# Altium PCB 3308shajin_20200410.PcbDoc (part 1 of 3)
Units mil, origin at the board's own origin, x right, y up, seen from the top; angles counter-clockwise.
Board outline 4724.41 x 2952.76 mil, 4 copper layers (Top, GND, Power, Bottom), stack 35.4 mil thick; 266 components, 266 nets, 1212 pads, 1516 vias.
Unrouted connection lines stored in the file: 149.
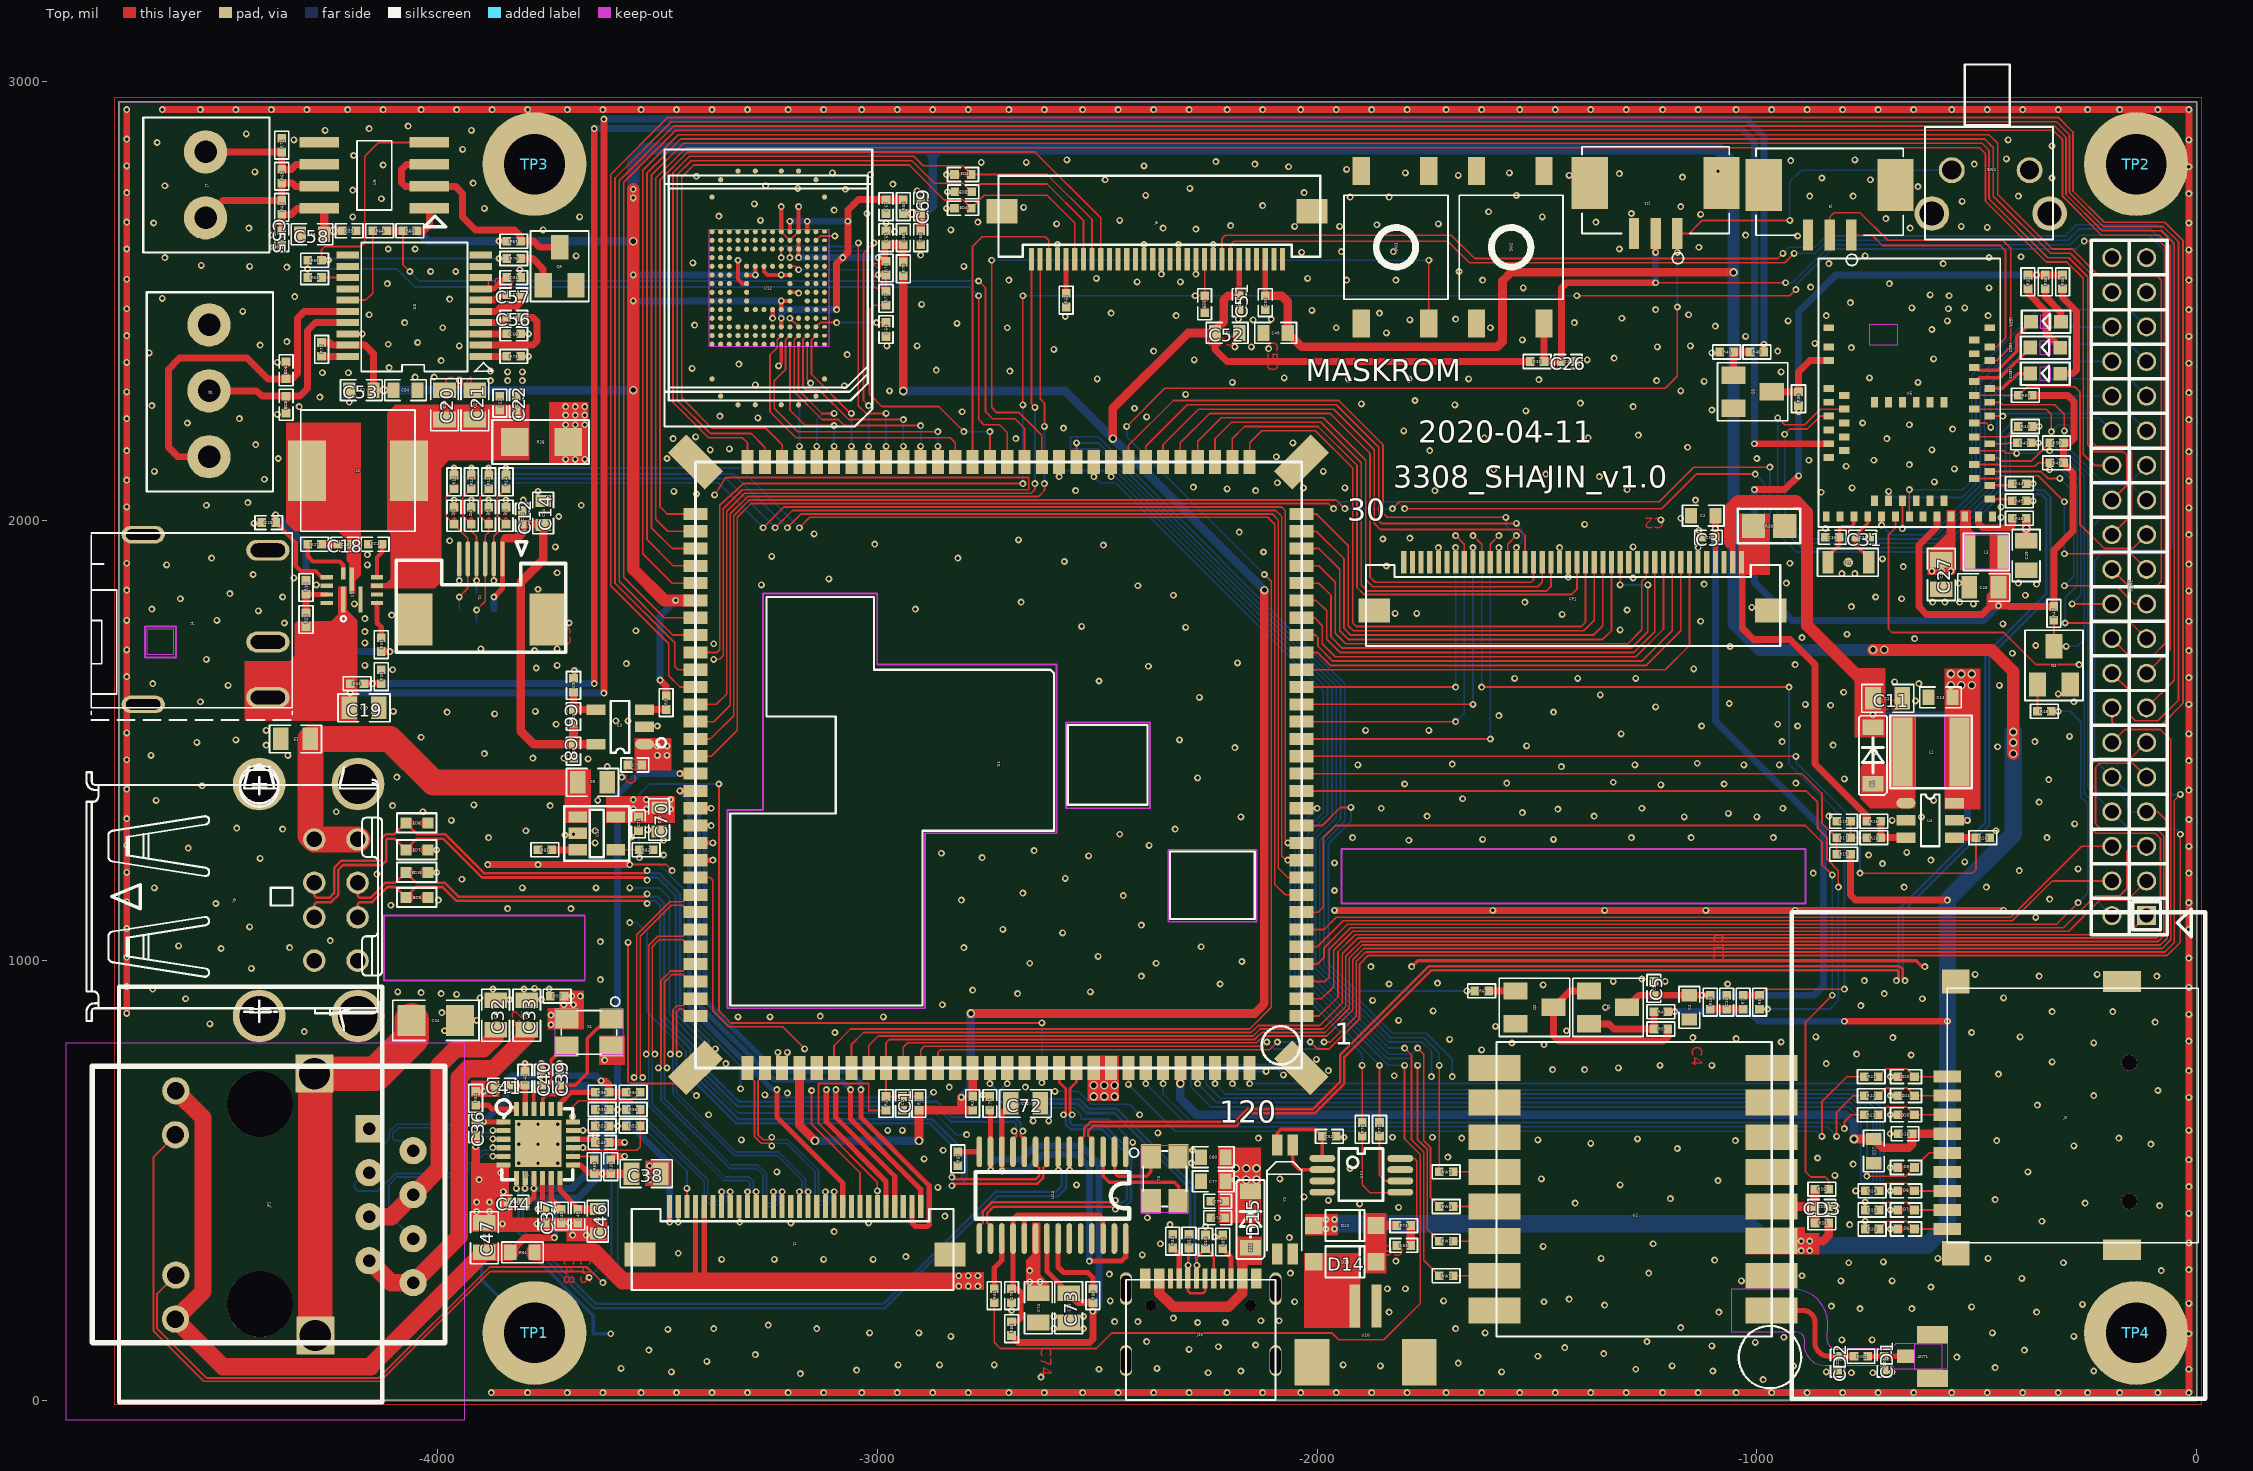
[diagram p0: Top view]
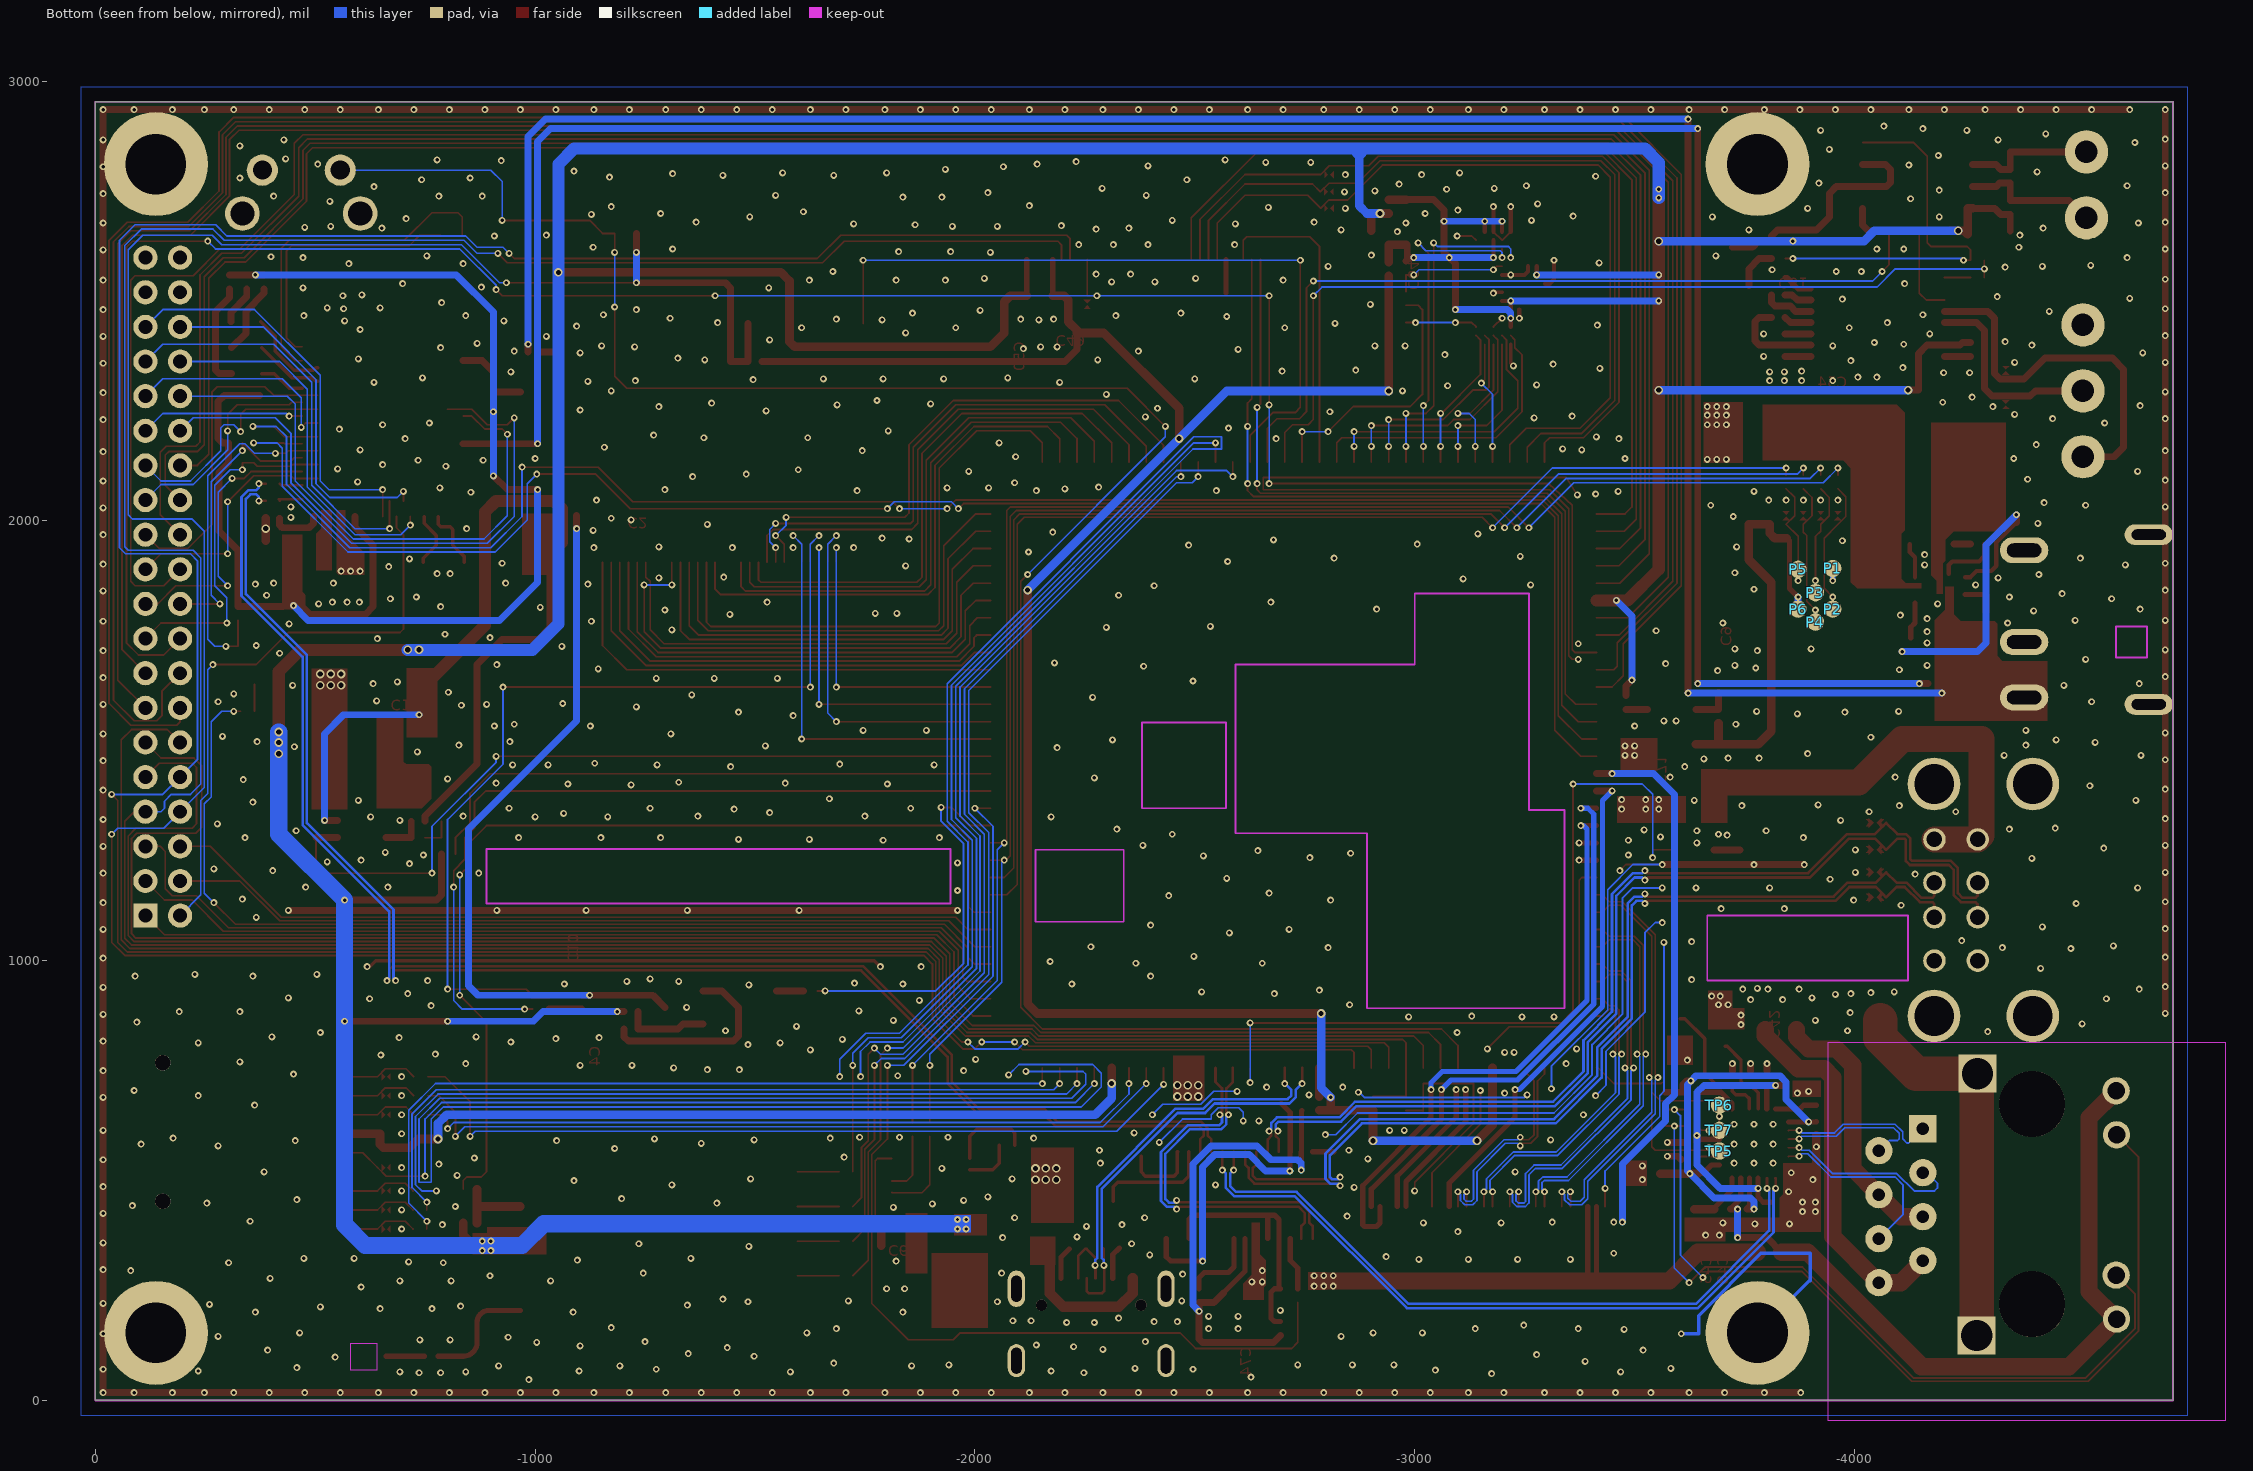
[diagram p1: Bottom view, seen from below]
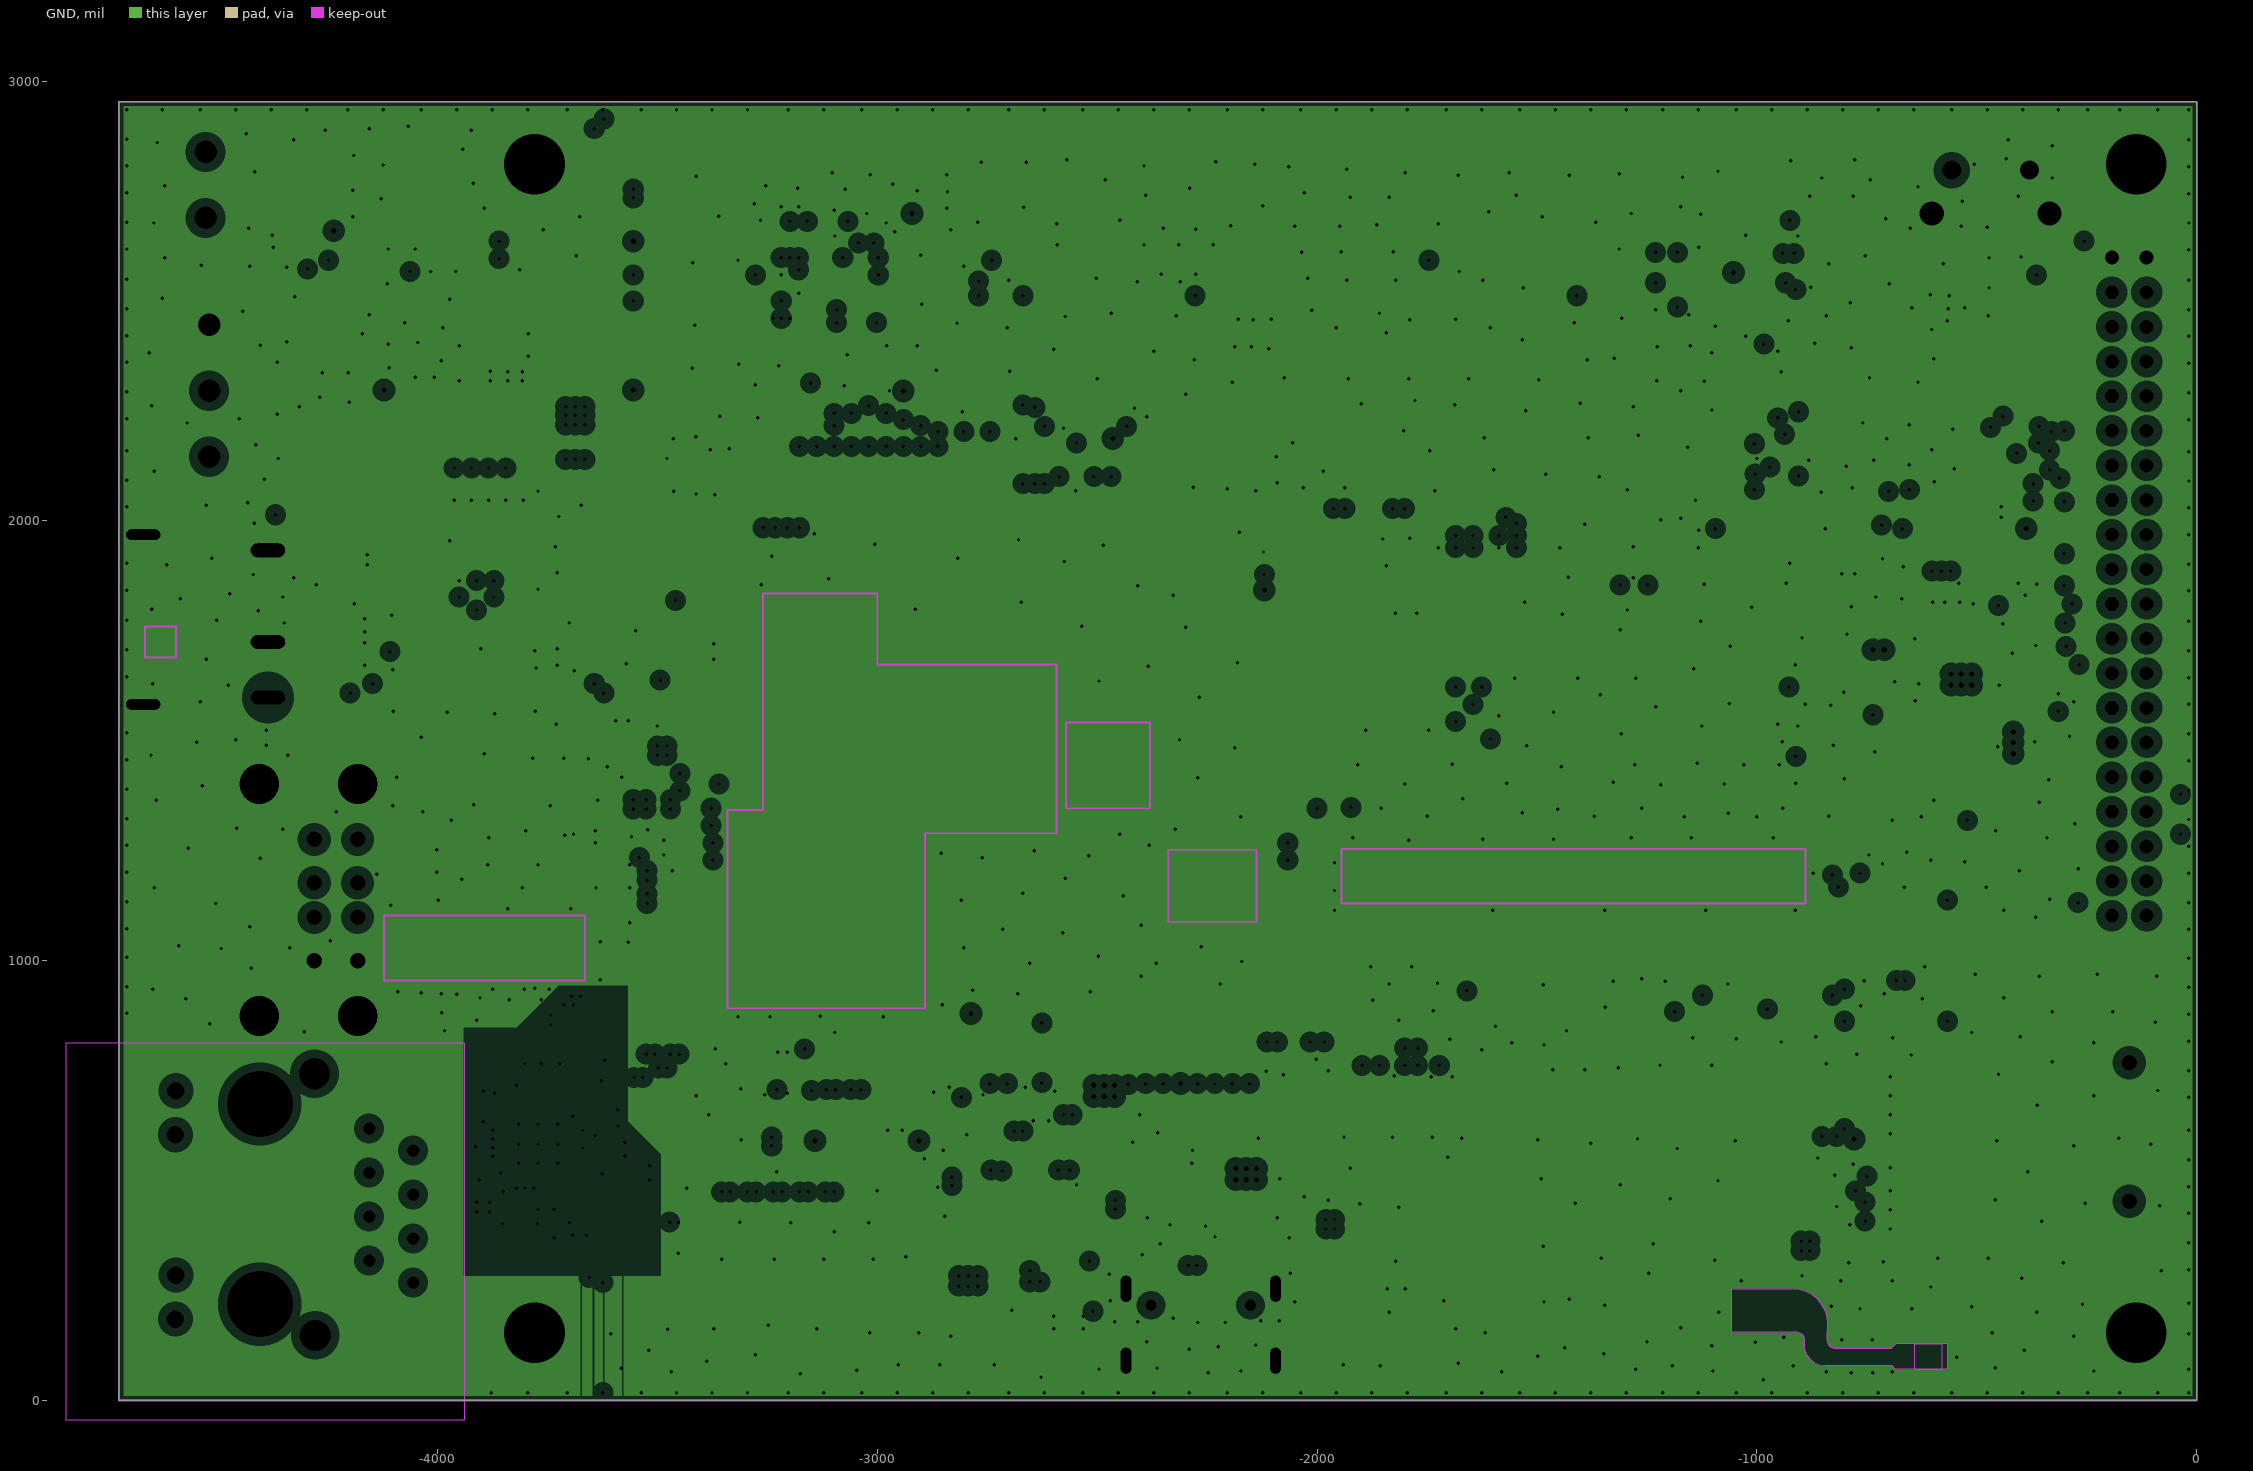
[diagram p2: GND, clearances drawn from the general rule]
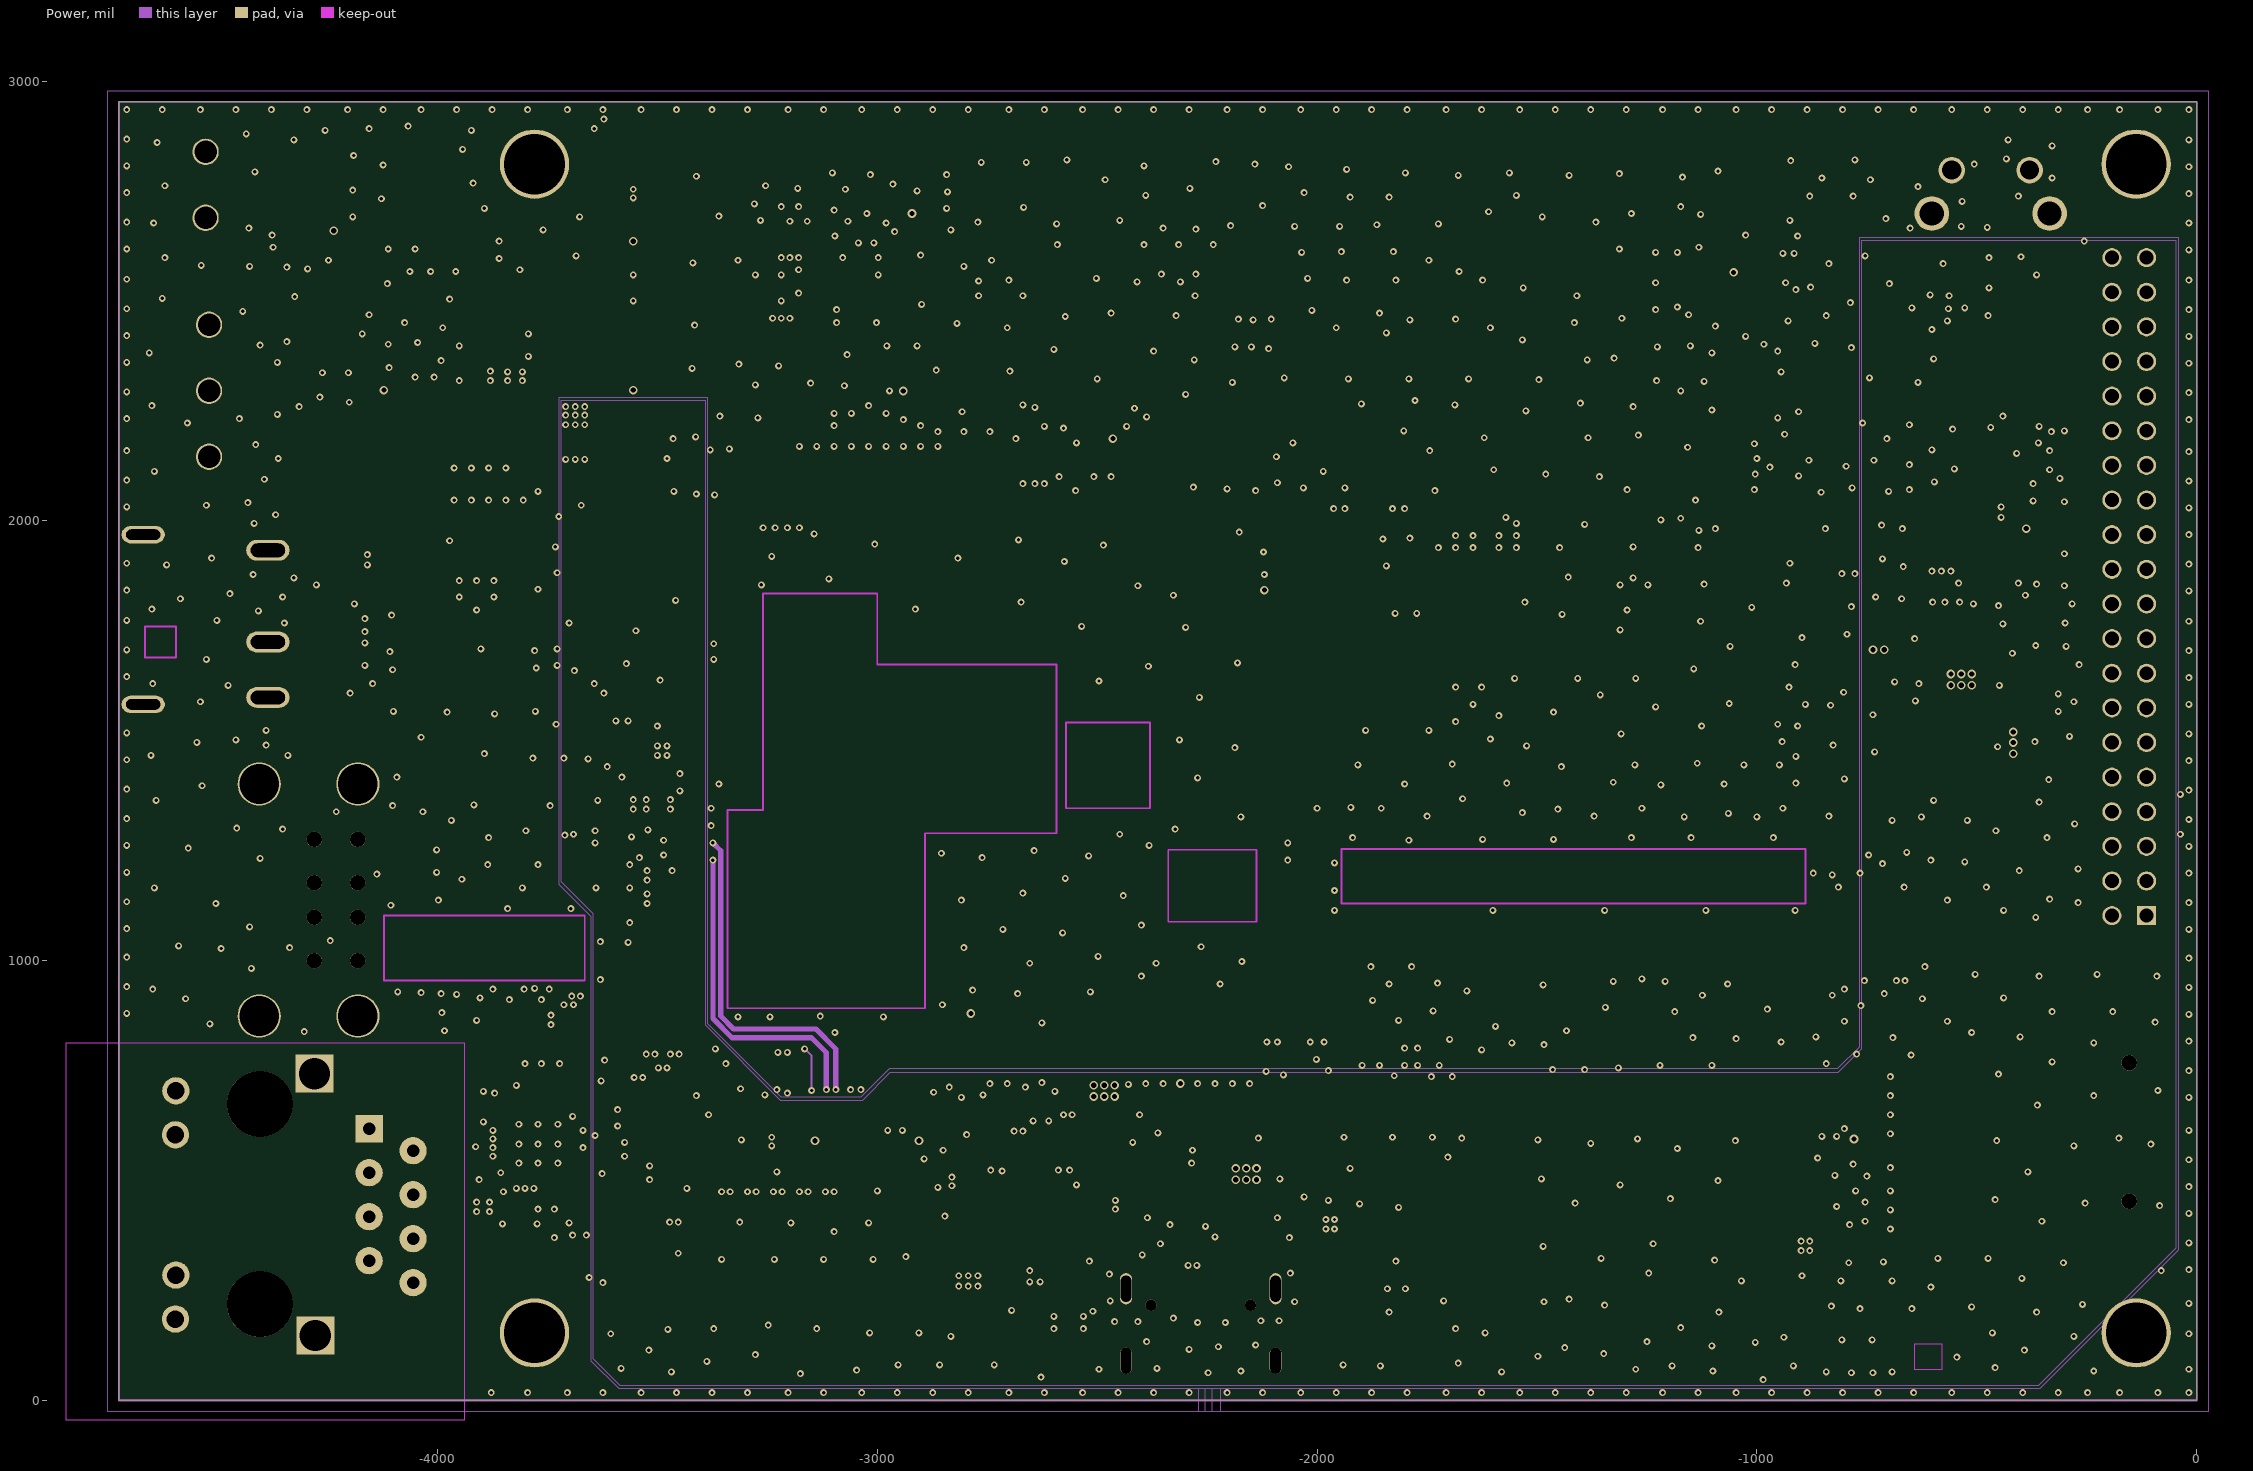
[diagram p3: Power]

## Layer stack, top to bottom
Solder Mask Top: solder mask 0.4, Solder Resist, Dk 3.5
Top: signal copper 1.35
Dielectric 1: dielectric 10, FR-4, Dk 4.3
GND: plane copper 1.35
Dielectric2: dielectric 10, FR-4, Dk 4.3
Power: signal copper 1.35
Dielectric3: dielectric 10, FR-4, Dk 4.3
Bottom: signal copper 1.35
Solder Mask Bottom: solder mask 0.4, Solder Resist, Dk 3.5

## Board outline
-4724.41,2952.76 0,2952.76 0,0 -4724.41,0

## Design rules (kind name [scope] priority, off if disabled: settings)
Clearance "Clearance - Default - DEFAULT- SMD" [IsVia vs IsSMTPin] p1: gap=0 ignorepadtopadclearanceinfootprint=FALSE
Clearance "Clearance - Default - DEFAULT - Via" [IsVia vs IsVia] p2: gap=0 ignorepadtopadclearanceinfootprint=FALSE
Clearance "Clearance - Default - DEFAULT - Net" [All] p3: gap=3.94 ignorepadtopadclearanceinfootprint=FALSE except(0: Arc-Hole Track-Hole SMDPad-Hole THPad-Hole Via-Hole Fill-Hole Poly-Hole Region-Hole Text-Hole; 5.91: Arc-Fill Arc-Poly Arc-Region Track-Fill Track-Poly Track-Region SMDPad-Fill SMDPad-Poly SMDPad-Region THPad-Fill THPad-Poly THPad-Region Via-Fill Via-Poly Via-Region; 10: Fill-Fill Fill-Poly Fill-Region Poly-Poly Poly-Region Region-Region Text-Text)
ComponentClearance "ComponentClearance - Default - DEFAULT" [All] p1: gap=0 collisioncheckmode=3 verticalgap=10 showdistances=FALSE
FanoutControl Fanout_Small [(CompPinCount < 5)] p3: bgadir=Out bgaviamode=Centered fanoutstyle=Auto fanoutdirection=OutThenIn viagrid=1 // Fanout_Small (Default Rule)
FanoutControl Fanout_SOIC [IsSOIC] p4: bgadir=Out bgaviamode=Centered fanoutstyle=Auto fanoutdirection=Alternating viagrid=1 // Fanout_SOIC (Default Rule)
HoleToHoleClearance "HoleToHoleClearance - Default - DEFAULT" [All] p1: gap=0 allowstackedmicrovias=TRUE
Length "Default Length" [All] p1: maxlimit=50000 minlimit=0
MaxMinImpedance "Default Impedance" [All] p1: minimum=50.00 maximum=150.0
ParallelSegment "Default Parallel Segment Adjasent" [All] p1: limit=1000 gap=200
ParallelSegment "Default Parallel Segment Same Layer" [All] p2: limit=1000 gap=200
PlaneClearance [All] p1: clearance=20
PlaneConnect "Default PlaneConnect" [All] p1: planeconnectstyle=Relief reliefexpansion=20 reliefentries=0 reliefconductorwidth=15 reliefairgap=10
PolygonConnect "PolygonConnect - Default SMT" [IsSMTPin] p1: connectstyle=Direct reliefconductorwidth=10 reliefentries=4 polygonreliefangle="45 Angle" airgapwidth=10
PolygonConnect "PolygonConnect - Default Pad" [All] p2: connectstyle=Relief reliefconductorwidth=15 reliefentries=4 polygonreliefangle="45 Angle" airgapwidth=10
RoutingLayers "RoutingLayers - Default - DEFAULT" [All] p1: top layer_v5=TRUE mid layer 1_v5=TRUE bottom layer_v5=TRUE
RoutingPriority "RoutingPriority - Default - DEFAULT" [All] p1: routingpriority=3
RoutingTopology "Default Routing Topology" [All] p1: topology=Shortest
RoutingVias "RoutingVias - Default - DEFAULT" [All] p1: holewidth=7.87 width=15.75 viastyle="Through Hole" minholewidth=7.87 minwidth=15.75 maxholewidth=7.87 maxwidth=15.75
SMDToCorner "SMDToCorner - Default - DEFAULT" [All] p1: distance=0
SolderMaskExpansion [All] p1: expansion=4
Width "Default Width" [All] p1: maxlimit=118.11 minlimit=3.94 preferedwidth=3.94
21 further rules are at their usual default settings.

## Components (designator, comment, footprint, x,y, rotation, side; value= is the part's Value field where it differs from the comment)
ANT1 "ANT_JACK" ANT_JACK -661.42,100.39 r0 top
C1 "C0402" C0402 -2942.91,675.2 r270 top
C2 "C0603" C0603 -1122.05,2011.81 r180 top
C3 "C0402" C0402 -1110.24,1962.6 r180 top
C4 "C0603" C0603 -1153.54,893.7 r270 top
C5 "C0402" C0402 -1234.25,937.01 r90 top
C6 "C0402" C0402 -3690.94,1555.12 r90 top
C7 "C0402" C0402 -3551.18,1444.88 r180 top
C8 "C0402" C0402 -3690.94,1476.38 r270 top
C9 "C0402" C0402 -3690.94,1625.98 r90 top
C10 "C0402" C0402 -1068.9,905.51 r90 top
C11 "C0805" C0805 -702.76,1596.46 r0 top
C12 "C0402" C0402 -3807.09,2007.87 r90 top
C13 "C0603" C0603 -582.68,1598.43 r180 top
C14 "C0603" C0603 -3759.84,2017.72 r90 top
C15 "C0402" C0402 -803.15,1316.93 r0 top
C16 "C0402" C0402 -663.39,606.3 r180 top
C17 "C0603" C0603 -734.25,566.93 r270 top
C18 "C0402" C0402 -4210.63,1946.85 r0 top
C19 "C0805" C0805 -4167.32,1574.8 r0 top
C20 "C0805" C0805 -3984.25,2263.78 r90 top
C21 "C0805" C0805 -3915.35,2263.78 r90 top
C22 "C0402" C0402 -3820.87,2267.72 r90 top
C23 "C0402" C0402 -3858.27,2267.72 r90 top
C24 "C0402" C0402 -4141.73,1946.85 r180 top
C25 "C0402" C0402 -4383.86,1996.06 r180 top
C26 "C0402" C0402 -1429.13,2362.2 r0 top
C27 "C0805" C0805 -580.71,1877.95 r270 top
C28 "C0805" C0805 -484.25,1848.43 r180 top
C29 "C0805" C0805 -387.8,1921.26 r270 top
C30 "C0402" C0402 -828.74,1962.6 r180 top
C31 "C0402" C0402 -759.84,1962.6 r0 top
C32 "C0805" C0805 -3868.11,875.98 r270 top
C33 "C0805" C0805 -3797.24,875.98 r270 top
C34 "C1206" C1206 -4003.94,864.17 r180 top
C35 "C0402" C0402 -3606.3,531.5 r90 top
C36 "C0402" C0402 -3913.39,618.11 r270 top
C37 "C0402" C0402 -3755.91,419.29 r270 top
C38 "C0805" C0805 -3525.59,515.75 r0 top
C39 "C0402" C0402 -3722.44,732.28 r90 top
C40 "C0402" C0402 -3763.78,732.28 r90 top
C41 "C0402" C0402 -3854.33,716.54 r180 top
C42 "C0402" C0402 -3801.18,732.28 r90 top
C43 "C0402" C0402 -3625.98,586.61 r0 top
C44 "C0402" C0402 -3824.8,450.79 r180 top
C45 "C0402" C0402 -3681.1,419.29 r270 top
C46 "C0603" C0603 -3635.83,407.48 r270 top
C47 "C0805" C0805 -3893.7,370.08 r90 top
C48 "C0402" C0402 -3718.5,419.29 r270 top
C49 "C0603" C0603 -2094.49,2427.17 r180 top
C50 "C0402" C0402 -2118.11,2496.06 r270 top
C51 "C0402" C0402 -2177.17,2496.06 r270 top
C52 "C0603" C0603 -2204.72,2427.17 r0 top
C53 "C0603" C0603 -4173.23,2297.24 r180 top
C54 "C0603" C0603 -4072.83,2297.24 r0 top
C55 "C0402" C0402 -4354.33,2643.7 r270 top
C56 "C0402" C0402 -3826.77,2462.6 r0 top
C57 "C0402" C0402 -3826.77,2513.78 r0 top
C58 "C0603" C0603 -4285.43,2651.57 r180 top
C59 "C0402" C0402 -4200.79,2659.45 r0 top
C60 "C0402" C0402 -3826.77,2425.2 r180 top
C61 "C0402" C0402 -3826.77,2553.15 r180 top
C62 "C0402" C0402 -1972.44,600.39 r180 top
C63 "C0402" C0402 -1803.15,352.36 r180 top
C64 "C0402" C0402 -2980.31,2435.04 r90 top
C65 "C0402" C0402 -2980.31,2643.7 r90 top
C66 "C0402" C0402 -2940.94,2643.7 r90 top
C67 "C0402" C0402 -2980.31,2714.57 r270 top
C68 "C0402" C0402 -2901.57,2643.7 r270 top
C69 "C0402" C0402 -2901.57,2714.57 r90 top
C70 "C0603" C0603 -3496.06,1320.87 r90 top
C71 "C0402" C0402 -3543.31,1311.02 r90 top
C72 "C0805" C0805 -2663.39,675.2 r0 top
C73 "C0805" C0805 -2564.96,210.63 r270 top
C74 "C0805" C0805 -2633.86,210.63 r270 top
C75 "C0402" C0402 -2744.09,675.2 r90 top
C76 "C0402" C0402 -2694.88,238.19 r270 top
C77 "C0603" C0603 -2236.22,498.03 r0 top
C78 "C0402" C0402 -2226.38,415.35 r0 top
C79 "C0402" C0402 -2226.38,452.76 r0 top
C80 "C0603" C0603 -2236.22,553.15 r0 top
CD1 "C0402" C0402 -710.63,84.65 r90 top
CD2 "C0402" C0402 -816.93,84.65 r90 top
CD3 "C0402" C0402 -852.36,440.94 r180 top
CON1 "DIP40_2X20" DIP40_2X20 -153.54,1456.69 r90 top
D1 "SOD123" SOD123 -736.22,1466.54 r270 top
D2 "ESD0402" ESD0402 -3962.6,2011.81 r90 top
D3 "ESD0402" ESD0402 -3844.49,2011.81 r90 top
D4 "ESD0402" ESD0402 -3923.23,2011.81 r90 top
D5 "ESD0402" ESD0402 -3883.86,2011.81 r90 top
D6 "ESD0402" ESD0402 -661.42,389.76 r180 top
D7 "ESD0402" ESD0402 -661.42,433.07 r180 top
D8 "ESD0402" ESD0402 -661.42,476.38 r180 top
D9 "ESD0402" ESD0402 -661.42,529.53 r180 top
D10 "ESD0402" ESD0402 -661.42,649.61 r180 top
D11 "ESD0402" ESD0402 -661.42,692.91 r180 top
D12 "ESD0402" ESD0402 -661.42,736.22 r180 top
D13 "SOD_123" SOD_123 -1937.01,397.64 r0 top
D14 "SOD_123" SOD_123 -1937.01,314.96 r0 top
D15 "SOD123" SOD123 -2151.57,411.42 r270 top
D16 "C0402" C0402 -2253.94,360.24 r90 top
D17 "C0402" C0402 -2291.34,362.2 r90 top
E1 "C0805" C0805 -4322.83,1503.94 r180 top
E2 "C0805" C0805 -3647.64,1405.51 r0 top
ED1 "ESD0402" ESD0402 -2255.91,2492.13 r270 top
ED2 "ESD0402" ESD0402 -2805.12,2787.4 r0 top
ED3 "ESD0402" ESD0402 -2805.12,2748.03 r180 top
ED4 "ESD0402" ESD0402 -2805.12,2710.63 r0 top
ED5 "ESD0402" ESD0402 -4344.49,2263.78 r270 top
ED6 "ESD0402" ESD0402 -4344.49,2342.52 r90 top
ED7 "E0402N" E0402N -4047.24,1251.97 r0 top
ED8 "E0402N" E0402N -4047.24,1312.99 r0 top
ED9 "E0402N" E0402N -4047.24,1143.7 r0 top
ED10 "E0402N" E0402N -4047.24,1200.79 r0 top
FP1 "FPC40PIN-0.5MM-FPC-BOTTOM" FPC40PIN-0.5MM-FPC-BOTTOM -1035.43,1905.51 r0 top
J1 "FPC30R_0R50_DOWN" FPC30R_0R50_DOWN -2901.57,440.94 r0 top
J2 "FPC6-0.5MM-2660H" FPC6-0.5MM-2660H -3901.57,1913.39 r0 top
J3 "TF-CKT01-009D" TF-CKT01-009D -153.54,610.24 r0 top
J4 "DC-044A" DC-044A -4787.4,1724.41 r270 top
J5 "CON3X1X1.25-HS" CON3X1X1.25-HS -834.65,2649.61 r90 top
J6 "FPC30R_0R50_DOWN" FPC30R_0R50_DOWN -2649.61,2594.49 r180 top
J7 "2PIN_3_81" 2PIN_3_81 -4527.56,2688.98 r90 top
J8 "3PIN_3_81" 3PIN_3_81 -4519.69,2145.67 r90 top
J9 "USB-AF-DUAL" USB-AF-DUAL -4405.51,1137.8 r0 top
J10 "TYPEC-16PIN-SMD1" TYPEC-16PIN-SMD1 -2094.49,90.55 r0 top
J11 "CON3X1X1.25-HS" CON3X1X1.25-HS -1230.31,2653.54 r90 top
JP1 "RJ-45-HR911105B" RJ-45-HR911105B -4374.02,440.94 r90 top
L1 "IND-4X4" IND-4X4 -604.33,1474.41 r180 top
L2 "0624_66X70" 0624_66X70 -4181.1,2114.17 r0 top
L3 "IND-2520" IND-2520 -478.35,1929.13 r0 top
LED1 "LED0603" LED0603 -342.52,2452.76 r180 top
LED2 "LED0603" LED0603 -344.49,2393.7 r180 top
LED3 "LED0603" LED0603 -344.49,2334.65 r180 top
P1 "T-1" T-1 -3950.79,1891.73 r180 bottom
P2 "T-1" T-1 -3950.79,1799.21 r180 bottom
P3 "T-1" T-1 -3911.42,1836.61 r180 bottom
P4 "T-1" T-1 -3911.42,1769.68 r180 bottom
P5 "T-1" T-1 -3872.05,1889.76 r180 bottom
P6 "T-1" T-1 -3872.05,1799.21 r180 bottom
Q1 "SOT23" SOT23 -1338.58,893.7 r270 top
Q2 "SOT23" SOT23 -1505.91,893.7 r270 top
Q3 "SOT23" SOT23 -1009.84,2293.31 r270 top
Q4 "SOT23" SOT23 -324.8,1671.26 r0 top
Q5 "SOT23" SOT23 -3722.44,2578.74 r0 top
R1 "R0402" R0402 -2905.51,675.2 r90 top
R2 "R0402" R0402 -2783.46,675.2 r90 top
R3 "R0402" R0402 -2980.31,675.2 r270 top
R4 "R0402" R0402 -1218.5,883.86 r180 top
R5 "R0402" R0402 -1218.5,844.49 r0 top
R6 "R0402" R0402 -1625.98,931.1 r180 top
R7 "R0402" R0402 -1031.5,905.51 r270 top
R8 "R0402" R0402 -994.09,905.51 r270 top
R9 "R0402" R0402 -3480.31,1586.61 r270 top
R10 "R0402" R0402 -1106.3,905.51 r270 top
R11 "R0402" R0402 -3962.6,2088.58 r270 top
R12 "R0402" R0402 -3883.86,2088.58 r270 top
R13 "R0402" R0402 -3923.23,2088.58 r270 top
R14 "R0402" R0402 -3844.49,2088.58 r270 top
R15 "R0402" R0402 -734.25,1316.93 r180 top
R16 "R0402" R0402 -486.22,1279.53 r180 top
R17 "R0402" R0402 -803.15,1279.53 r0 top
R18 "R0402" R0402 -734.25,1279.53 r0 top
R19 "R0402" R0402 -803.15,1242.13 r0 top
R20 "R0805" R0805 -972.44,1988.19 r0 top
R21 "R0402" R0402 -740.16,736.22 r0 top
R22 "R0402" R0402 -740.16,692.91 r0 top
R23 "R0402" R0402 -740.16,649.61 r0 top
R24 "R0402" R0402 -738.19,476.38 r0 top
R25 "R0402" R0402 -738.19,433.07 r0 top
R26 "R0402" R0402 -738.19,389.76 r0 top
R27 "R0402" R0402 -4279.53,1946.85 r0 top
R28 "R1206" R1206 -3765.75,2179.13 r180 top
R29 "R0402" R0402 -4299.21,1775.59 r270 top
R30 "R0402" R0402 -4299.21,1848.43 r270 top
R32 "R0402" R0402 -1500,2362.2 r0 top
R33 "R0402" R0402 -4127.95,1718.5 r90 top
R34 "R0402" R0402 -4183.07,1629.92 r180 top
R35 "R0402" R0402 -4127.95,1645.67 r270 top
R36 "R0402" R0402 -344.49,2543.31 r90 top
R37 "R0402" R0402 -383.86,2543.31 r90 top
R38 "R0402" R0402 -305.12,2543.31 r90 top
R39 "R0402" R0402 -905.51,2277.56 r270 top
R40 "R0402" R0402 -1000,2383.86 r0 top
R41 "R0402" R0402 -1068.9,2383.86 r180 top
R42 "R0402" R0402 -389.76,2214.57 r180 top
R43 "R0402" R0402 -391.73,2177.17 r180 top
R44 "R0402" R0402 -403.54,2084.65 r0 top
R45 "R0402" R0402 -403.54,2045.28 r0 top
R46 "R0402" R0402 -403.54,2005.91 r0 top
R47 "R0402" R0402 -324.8,1789.37 r90 top
R48 "R0402" R0402 -346.46,1566.93 r0 top
R49 "R0402" R0402 -318.9,2131.89 r180 top
R50 "R0402" R0402 -318.9,2177.17 r180 top
R51 "R0402" R0402 -389.76,2285.43 r0 top
R52 "R0402" R0402 -3555.12,624.02 r180 top
R53 "R0402" R0402 -3625.98,624.02 r0 top
R54 "R0402" R0402 -3913.39,687.01 r270 top
R55 "R0402" R0402 -3625.98,661.42 r0 top
R56 "R0402" R0402 -3555.12,661.42 r180 top
R57 "R0402" R0402 -3728.35,919.29 r0 top
R58 "R0402" R0402 -3625.98,700.79 r0 top
R59 "R0402" R0402 -3643.7,531.5 r270 top
R60 "R0402" R0402 -3555.12,700.79 r180 top
R61 "R0603" R0603 -3807.09,336.61 r0 top
R62 "R0402" R0402 -2570.87,2501.97 r270 top
R63 "R0402" R0402 -4279.53,2553.15 r180 top
R64 "R0402" R0402 -4131.89,2659.45 r0 top
R65 "R0402" R0402 -4279.53,2592.52 r180 top
R66 "R0402" R0402 -4062.99,2659.45 r180 top
R67 "R0402" R0402 -3826.77,2635.83 r0 top
R68 "R0402" R0402 -4354.33,2712.6 r90 top
R69 "R0402" R0402 -4354.33,2783.46 r90 top
R70 "R0402" R0402 -3826.77,2596.46 r0 top
R71 "R0402" R0402 -4354.33,2854.33 r90 top
R72 "R0402" R0402 -4263.78,2389.76 r270 top
R73 "R0402" R0402 -3826.77,2374.02 r0 top
R74 "R0402" R0402 -1803.15,397.64 r180 top
R75 "R0402" R0402 -1858.27,616.14 r90 top
R76 "R0402" R0402 -1897.64,616.14 r90 top
R77 "R0402" R0402 -2980.31,2505.91 r90 top
R78 "R0402" R0402 -2980.31,2574.8 r270 top
R79 "R0402" R0402 -2940.94,2572.83 r90 top
R80 "R0402" R0402 -2940.94,2714.57 r90 top
R81 "R0402" R0402 -2734.25,238.19 r90 top
R82 "R0402" R0402 -3525.59,1251.97 r180 top
R83 "R0402" R0402 -3755.91,1251.97 r0 top
R84 "R0402" R0402 -2328.74,362.2 r270 top
R85 "R0402" R0402 -2214.57,360.24 r270 top
R86 "R0402" R0402 -2694.88,163.39 r270 top
R87 "R0402" R0402 -2816.93,549.21 r90 top
R88 "R0402" R0402 -2509.84,238.19 r90 top
RD1 "R0402" R0402 -852.36,403.54 r0 top
RD2 "R0402" R0402 -852.36,480.31 r0 top
RW1 "R0402" R0402 -763.78,100.39 r0 top
RW2 "R0402" R0402 -1706.69,283.46 r180 top
RW3 "R0402" R0402 -1706.69,362.2 r180 top
RW4 "R0402" R0402 -1706.69,440.94 r180 top
RW5 "R0402" R0402 -1706.69,519.68 r180 top
SW2 "KEY6X6X45" KEY6X6X45 -1561.02,2624.02 r90 top
SW3 "KEY6X6X45" KEY6X6X45 -1822.83,2624.02 r90 top
SW4 "TS-1038" TS-1038 -468.5,2797.24 r180 top
TP1 "HOLE$2F$PTH$2F$R6D3.5" HOLE$2F$PTH$2F$R6D3.5 -3779.53,153.54 r0 top
TP2 "HOLE$2F$PTH$2F$R6D3.5" HOLE$2F$PTH$2F$R6D3.5 -137.8,2811.02 r0 top
TP3 "HOLE$2F$PTH$2F$R6D3.5" HOLE$2F$PTH$2F$R6D3.5 -3779.53,2811.02 r0 top
TP4 "HOLE$2F$PTH$2F$R6D3.5" HOLE$2F$PTH$2F$R6D3.5 -137.8,153.54 r0 top
TP5 "T-1" T-1 -3692.91,566.93 r180 bottom
TP6 "T-1" T-1 -3692.91,671.26 r180 bottom
TP7 "T-1" T-1 -3692.91,614.17 r180 bottom
U1 "35X35_MOUDEL_124SMD" 35X35_MOUDEL_124SMD -2035.43,874.02 r90 top
U2 "LORA" LORA -966.54,204.72 r180 top
U3 "SOT_23_5" SOT_23_5 -3584.65,1531.5 r180 top
U4 "SOT26" SOT26 -661.42,1358.27 r0 top
U5 "QFN12_2R00X3R00X1R00" QFN12_2R00X3R00X1R00 -4194.88,1842.52 r90 top
U6 "MDBT50Q" MDBT50Q -860.24,1986.22 r0 top
U7 "QFN24" QFN24 -3773.62,588.58 r270 top
U8 "SSOP20_1" SSOP20_1 -3901.57,2374.02 r90 top
U9 "SOP8-255-50" SOP8-255-50 -4143.7,2785.43 r90 top
U10 "SMD-2P-1.25" SMD-2P-1.25 -1889.76,204.72 r0 top
U11 "MSOP8" MSOP8 -1899.61,511.81 r270 top
U12 "BGA169_18R00X14R00X1R20" BGA169_18R00X14R00X1R20 -3248.03,2529.53 r180 top
U13 "SOT23-5" SOT23-5 -3637.8,1289.37 r270 top
U14 "SSOP28-HUB" SSOP28-HUB -2590.55,462.6 r270 top
X1 "CRY-D3225" CRY-D3225 -3655.51,836.61 r180 top
Y1 "CRY-3215" CRY-3215 -838.58,1905.51 r0 top
Y2 "CRY-MC146" CRY-MC146 -2072.83,444.88 r270 top
Y3 "CRY-D3225" CRY-D3225 -2346.46,503.94 r270 top

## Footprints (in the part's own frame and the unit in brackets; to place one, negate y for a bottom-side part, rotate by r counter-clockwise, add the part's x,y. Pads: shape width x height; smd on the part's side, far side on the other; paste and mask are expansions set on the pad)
2PIN_3_81 [mm]
  round 2.5 / inner round 1.524 / far side round 2.5 hole 1.3: 1(0,0) 2(3.81,0)
  silkscreen extent -2,-3.7 5.8,3.6
3PIN_3_81 [mm]
  round 2.5 / inner round 1.524 / far side round 2.5 hole 1.3: 1(0,0) 2(3.81,0) 3(7.62,0)
  silkscreen extent -2,-3.7 9.5,3.6
35X35_MOUDEL_124SMD [mm]
  rect 0.7x1.4 smd: 1(0,0) 2(1,0) 3(2,0) 4(3,0) 5(4,0) 6(5,0) 7(6,0) 8(7,0) 9(8,0) 10(9,0) 11(10,0) 12(11,0) 13(12,0) 14(13,0) 15(14,0) 16(15,0) 17(16,0) 18(17,0) 19(18,0) 20(19,0) 21(20,0) 22(21,0) 23(22,0) 24(23,0) 25(24,0) 26(25,0) 27(26,0) 28(27,0) 29(28,0) 30(29,0) 61(29,35) 62(28,35) 63(27,35) 64(26,35) 65(25,35) 66(24,35) 67(23,35) 68(22,35) 69(21,35) 70(20,35) 71(19,35) 72(18,35) 73(17,35) 74(16,35) 75(15,35) 76(14,35) 77(13,35) 78(12,35) 79(11,35) 80(10,35) 81(9,35) 82(8,35) 83(7,35) 84(6,35) 85(5,35) 86(4,35) 87(3,35) 88(2,35) 89(1,35) 90(0,35)
  rect 1.4x0.7 smd: 31(32,3) 32(32,4) 33(32,5) 34(32,6) 35(32,7) 36(32,8) 37(32,9) 38(32,10) 39(32,11) 40(32,12) 41(32,13) 42(32,14) 43(32,15) 44(32,16) 45(32,17) 46(32,18) 47(32,19) 48(32,20) 49(32,21) 50(32,22) 51(32,23) 52(32,24) 53(32,25) 54(32,26) 55(32,27) 56(32,28) 57(32,29) 58(32,30) 59(32,31) 60(32,32) 91(-3,32) 92(-3,31) 93(-3,30) 94(-3,29) 95(-3,28) 96(-3,27) 97(-3,26) 98(-3,25) 99(-3,24) 100(-3,23) 101(-3,22) 102(-3,21) 103(-3,20) 104(-3,19) 105(-3,18) 106(-3,17) 107(-3,16) 108(-3,15) 109(-3,14) 110(-3,13) 111(-3,12) 112(-3,11) 113(-3,10) 114(-3,9) 115(-3,8) 116(-3,7) 117(-3,6) 118(-3,5) 119(-3,4) 120(-3,3)
  rect 3x1.5 smd rot 45: 121(-2.99,0.02) 122(32,35.01)
  rect 3x1.5 smd rot 135: 123(31.99,0) 124(-2.99,35.01)
  silkscreen extent -3,0 32,35
0624_66X70 [mm]
  rect 2.2x3.5 smd: 1(-2.95,0) 2(2.95,0)
  silkscreen extent -3.3,-3.5 3.3,3.5
ANT_JACK [mm]
  rect 1x0.8 smd: 1(0,0)
  rect 1.8x1 smd: 2(1.53,1.24) 3(1.53,-1.28)
  Keep-Out Layer region: 0.515,0.73 2.065,0.73 2.065,-0.77 0.515,-0.77 0.515,0.73
BGA169_18R00X14R00X1R20 [mm]
  round 0.3 smd: 1(-1.75,6.75) 2(-0.75,6.75) 3(0.75,6.75) 4(1.75,6.75) 5(-2.75,6.25) 6(2.75,6.25) 7(-3.25,5.25) 8(3.25,5.25) 15(-0.25,3.25) 16(0.25,3.25) 17(0.75,3.25) 18(1.25,3.25) 19(1.75,3.25) 20(2.25,3.25) 21(2.75,3.25) 22(3.25,3.25) 24(-2.75,2.75) 25(-2.25,2.75) 26(-1.75,2.75) 27(-1.25,2.75) 28(-0.75,2.75) 29(-0.25,2.75) 30(0.25,2.75) 31(0.75,2.75) 32(1.25,2.75) 33(1.75,2.75) 34(2.25,2.75) 35(2.75,2.75) 36(3.25,2.75) 38(-2.75,2.25) 39(-2.25,2.25) 40(-1.75,2.25) 41(-1.25,2.25) 42(-0.75,2.25) 43(-0.25,2.25) 44(0.25,2.25) 45(0.75,2.25) 46(1.25,2.25) 47(1.75,2.25) 48(2.25,2.25) 49(2.75,2.25) 50(3.25,2.25) 52(-2.75,1.75) 53(-2.25,1.75) 54(-1.75,1.75) 55(2.25,1.75) 56(2.75,1.75) 57(3.25,1.75) 59(-2.75,1.25) 60(-2.25,1.25) 61(-1.25,1.25) 62(-0.75,1.25) 63(-0.25,1.25) 64(0.25,1.25) 65(0.75,1.25) 66(1.25,1.25) 67(2.25,1.25) 68(2.75,1.25) 69(3.25,1.25) 70(-3.25,0.75) 71(-2.75,0.75) 72(-2.25,0.75) 73(-1.25,0.75) 74(1.25,0.75) 75(2.25,0.75) 76(2.75,0.75) 77(3.25,0.75) 78(-3.25,0.25) 79(-2.75,0.25) 80(-2.25,0.25) 81(-1.25,0.25) 82(1.25,0.25) 83(2.25,0.25) 84(2.75,0.25) 85(3.25,0.25) 86(-3.25,-0.25) 87(-2.75,-0.25) 88(-2.25,-0.25) 89(-1.25,-0.25) 90(1.25,-0.25) 91(2.25,-0.25) 92(2.75,-0.25) 93(3.25,-0.25) 94(-3.25,-0.75) 95(-2.75,-0.75) 96(-2.25,-0.75) 97(-1.25,-0.75) 98(1.25,-0.75) 99(2.25,-0.75) 100(2.75,-0.75) 101(3.25,-0.75) 102(-3.25,-1.25) 103(-2.75,-1.25) 104(-2.25,-1.25) 105(-1.25,-1.25) 106(-0.75,-1.25) 107(-0.25,-1.25) 108(0.25,-1.25) 109(0.75,-1.25) 110(1.25,-1.25) 111(2.25,-1.25) 112(2.75,-1.25) 113(3.25,-1.25) 114(-3.25,-1.75) 115(-2.75,-1.75) 116(-2.25,-1.75) 117(2.25,-1.75) 118(2.75,-1.75) 119(3.25,-1.75) 120(-3.25,-2.25) 121(-2.75,-2.25) 122(-2.25,-2.25) 123(-1.75,-2.25) 124(-1.25,-2.25) 125(-0.75,-2.25) 126(-0.25,-2.25) 127(0.25,-2.25) 128(0.75,-2.25) 129(1.25,-2.25) 130(1.75,-2.25) 131(2.25,-2.25) 132(2.75,-2.25) 133(3.25,-2.25) 135(-2.75,-2.75) 136(-2.25,-2.75) 137(-1.75,-2.75) 138(-1.25,-2.75) 139(-0.75,-2.75) 140(-0.25,-2.75) 141(0.25,-2.75) 142(0.75,-2.75) 143(1.25,-2.75) 144(1.75,-2.75) 145(2.25,-2.75) 146(2.75,-2.75) 147(3.25,-2.75) 149(-2.75,-3.25) 150(-2.25,-3.25) 151(-1.75,-3.25) 152(-1.25,-3.25) 153(-0.75,-3.25) 154(-0.25,-3.25) 155(0.25,-3.25) 156(0.75,-3.25) 157(1.25,-3.25) 158(1.75,-3.25) 159(2.25,-3.25) 160(2.75,-3.25) 161(3.25,-3.25) 162(-3.25,-5.25) 163(3.25,-5.25) 164(-2.75,-6.25) 165(2.75,-6.25) 166(-1.75,-6.75) 167(-0.75,-6.75) 168(0.75,-6.75) 169(1.75,-6.75)
  oval 0.3x0.2 smd: 9(-3.25,3.25) 23(-3.25,2.75) 37(-3.25,2.25) 51(-3.25,1.75) 58(-3.25,1.25) 134(-3.25,-2.75) 148(-3.25,-3.25)
  oval 0.2x0.3 smd: 10(-2.75,3.25) 11(-2.25,3.25) 12(-1.75,3.25) 13(-1.25,3.25) 14(-0.75,3.25)
  silkscreen extent -6,-8 6,8
C0402 [mm]
  rect 0.5x0.5 smd: 1(-0.4,0) 2(0.4,0)
  silkscreen extent -0.8,-0.4 0.8,0.4
C0603 [mm]
  rect 0.7x0.9 smd: 1(-0.7,0) 2(0.7,0)
  silkscreen extent -1.2,-0.6 1.2,0.6
C0805 [mm]
  rect 0.9x1.3 smd: 1(-0.85,0) 2(0.85,0)
  silkscreen extent -1.5,-0.8 1.5,0.8
C1206 [mm]
  rect 1.6x1.8 smd: 1(-1.4,0) 2(1.4,0)
  silkscreen extent -2.49,-1.17 2.49,1.17
CON3X1X1.25-HS [mm]
  rect 1.8x0.6 smd: 1(0,-1.25) 2(0,0) 3(0,1.25)
  rect 3x2.1 smd: 4(2.9,-3.8) 5(2.9,3.8)
  silkscreen extent -1.75,-4.26 5,4.26
CRY-3215 [mm]
  rect 0.65x1.3 smd: 1(0,0) 2(2.35,0)
  round 0.55 smd: 3(1.175,0)
  silkscreen extent -0.6,-0.8 2.9,0.8
CRY-D3225 [mm]
  rect 1.4x1.15 smd: 1(-1.3,-0.8) 2(1.3,-0.8) 3(1.3,0.8) 4(-1.3,0.8)
  Top keep-out region: -1.95,1.3 1.95,1.3 1.95,-1.35 -1.95,-1.35 -1.95,1.3
  silkscreen extent -1.77,-2.04 1.6,1.25
CRY-MC146 [mm]
  rect 1.2x0.6 smd: 1(-3.45,-0.46) 2(-3.45,0.44) 3(2.85,0.44) 4(2.85,-0.46)
  silkscreen extent -2.49,-1.04 2.65,0.96
DC-044A [mm]
  oval 1.2x2.5 / inner oval 1.2x2.5 / far side oval 1.5x2.8 hole 0.787 slot 1.981 at 90 deg: 1(3.2,10.2) 2(-5.3,10.2) 3(0,10.2)
  oval 1x2.5 / inner oval 1x2.5 / far side oval 1.2x2.8 hole 0.6 slot 1.981 at 90 deg: 4(-6.2,3) 5(3.6,3)
  Top keep-out region: -0.759,4.741 0.741,4.741 0.741,3.241 -0.759,3.241 -0.759,4.741
  silkscreen extent -6.3,0 4.5,11.6
DIP40_2X20 [mm]
  rect 1.1x1.1 / inner rect 1.1x1.1 / far side rect 1.4x1.4 hole 0.8: 1(-9,-1)
  round 1.1 / inner round 1.1 / far side round 1.4 hole 0.8: 2(-9,1) 3(-7,-1) 4(-7,1) 5(-5,-1) 6(-5,1) 7(-3,-1) 8(-3,1) 9(-1,-1) 10(-1,1) 11(1,-1) 12(1,1) 13(3,-1) 14(3,1) 15(5,-1) 16(5,1) 17(7,-1) 18(7,1) 19(9,-1) 20(9,1) 21(11,-1) 22(11,1) 23(13,-1) 24(13,1) 25(15,-1) 26(15,1) 27(17,-1) 28(17,1) 29(19,-1) 30(19,1) 31(21,-1) 32(21,1) 33(23,-1) 34(23,1) 35(25,-1) 36(25,1) 37(27,-1) 38(27,1) 39(29,-1) 40(29,1)
  silkscreen extent -10.22,-3.57 30,2.2
E0402N [mil]
  rrect0% 25x25 smd: 1(-25,0) 2(25,0)
  Top region: -14,-10.5 -3.25,0.25 -14.25,11.25 -14.25,-10 -14,-10 -14,-10.5
  Top region: -12,-6.5 -5.5,0 -12.25,6.75 -12.25,-6 -12,-6 -12,-6.5
  Top region: 14.5,11 3.75,0.25 14.75,-10.75 14.75,10.5 14.5,10.5 14.5,11
  Top region: 12.5,7 6,0.5 12.75,-6.25 12.75,6.5 12.5,6.5 12.5,7
  Top lines w2: -19.5,-7 -12,-7 ; -19.5,7.5 -17.5,7.5 -12,7.5 ; -18,-5.5 -10.5,-5.5 ; -18,6 -10.5,6 ; -17,4.5 -9.5,4.5 ; -16.5,-4 -9,-4 ; -16,3.5 -8.5,3.5 ; -15.5,-2.5 -8,-2.5 ; -15,2.5 -7.5,2.5 ; -14,-1.5 -6.5,-1.5 ; -13.5,1.5 -6,1.5 ; -13,-0.5 -5.5,-0.5 ; -12.5,0.5 -5,0.5 ; 5.5,0 13,0 ; 6,1 13.5,1 ; 6.5,-1 14,-1 ; 7,2 14.5,2 ; 8,-2 15.5,-2 ; 8.5,3 16,3 ; 9,-3 16.5,-3 ; 9.5,4.5 17,4.5 ; 10,-4 17.5,-4 ; 11,-5.5 18.5,-5.5 ; 11,6 18.5,6 ; 12.5,-7 20,-7 ; 12.5,7.5 20,7.5
  silkscreen extent -45,-22 45,22
ESD0402 [mm]
  rrect0% 0.5x0.5 smd: 1(-0.499,0) 2(0.479,0)
  Top region: -0.267,0.203 -0.064,0 -0.267,-0.203 -0.267,0.203
  Top region: 0.241,0.178 0.064,0 0.241,-0.178 0.241,0.178
  silkscreen extent -0.9,-0.4 0.89,0.4
FPC6-0.5MM-2660H [mm]
  oval 0.254x2.032 smd: 1(-1.25,0) 2(-0.75,0) 3(-0.25,0) 4(0.25,0) 5(0.75,0) 6(1.25,0)
  rect 2x3 smd paste-0.484 mask-0.484: 7(3.8,-3.5) 8(-3.8,-3.5)
  silkscreen extent -4.9,-5.39 4.9,1
FPC30R_0R50_DOWN [mm]
  rect 0.3x1.3 smd: 1(-14.5,0) 2(-14,0) 3(-13.5,0) 4(-13,0) 5(-12.5,0) 6(-12,0) 7(-11.5,0) 8(-11,0) 9(-10.5,0) 10(-10,0) 11(-9.5,0) 12(-9,0) 13(-8.5,0) 14(-8,0) 15(-7.5,0) 16(-7,0) 17(-6.5,0) 18(-6,0) 19(-5.5,0) 20(-5,0) 21(-4.5,0) 22(-4,0) 23(-3.5,0) 24(-3,0) 25(-2.5,0) 26(-2,0) 27(-1.5,0) 28(-1,0) 29(-0.5,0) 30(0,0)
  rect 1.8x1.4 smd: 31(1.7,-2.775) 32(-16.2,-2.775)
  silkscreen extent -16.68,-4.82 1.9,-0.15
FPC40PIN-0.5MM-FPC-BOTTOM [mm]
  rect 0.3x1.3 smd: 1(0,0) 2(-0.5,0) 3(-1,0) 4(-1.5,0) 5(-2,0) 6(-2.5,0) 7(-3,0) 8(-3.5,0) 9(-4,0) 10(-4.5,0) 11(-5,0) 12(-5.5,0) 13(-6,0) 14(-6.5,0) 15(-7,0) 16(-7.5,0) 17(-8,0) 18(-8.5,0) 19(-9,0) 20(-9.5,0) 21(-10,0) 22(-10.5,0) 23(-11,0) 24(-11.5,0) 25(-12,0) 26(-12.5,0) 27(-13,0) 28(-13.5,0) 29(-14,0) 30(-14.5,0) 31(-15,0) 32(-15.5,0) 33(-16,0) 34(-16.5,0) 35(-17,0) 36(-17.5,0) 37(-18,0) 38(-18.5,0) 39(-19,0) 40(-19.5,0)
  rect 1.8x1.4 smd: 41(-21.2,-2.775) 42(1.7,-2.775)
  silkscreen extent -21.68,-4.82 2.25,-0.15
HOLE$2F$PTH$2F$R6D3.5 [mm]
  round 6 / inner round 4 / far side round 6 hole 3.5: 1(0,0)
IND-4X4 [mm]
  rect 1.15x4 smd: 1(-1.65,0) 2(1.65,0)
  silkscreen extent -2.35,-2.1 2.35,2.1
IND-2520 [mm]
  rect 0.6x2 smd: 1(0.947,0.006) 2(-0.953,0.006)
  Top keep-out region: -1.25,1 1.25,1 1.25,-1 -1.25,-1 -1.25,1
  silkscreen extent -1.33,-1.07 1.33,1.08
KEY6X6X45 [mm]
  rect 1.6x1 smd: 1(-4.45,1.95) 2(-4.45,-1.95) 3(4.35,-1.95) 4(4.35,1.95)
  silkscreen extent -3.05,-3.05 2.95,2.95
LED0603 [mm]
  rect 0.8x0.8 smd: 1(-0.868,0.002) 2(0.869,-0.001)
  Top keep-out region: -0.3,0.4 0.3,0.4 0.3,-0.4 -0.3,-0.4 -0.3,0.4
  silkscreen extent -1.41,-0.65 1.41,0.65
LORA [mm]
  rect 3x1.5 smd: 1(0,0) 2(0,-2) 3(0,-4) 4(0,-6) 5(0,-8) 6(0,-10) 7(0,-12) 8(0,-14) 9(16,-14) 10(16,-12) 11(16,-10) 12(16,-8) 13(16,-6) 14(16,-4) 15(16,-2) 16(16,0)
  silkscreen extent -1.7,-15.5 15.9,4.5
MDBT50Q [mm]
  rect 0.6x0.4 smd: 1(0.6,11.5) 2(0.6,10.4) 3(0.6,9.6) 4(0.6,8) 5(1.5,7.6) 6(0.6,7.2) 7(1.5,6.8) 8(0.6,6.4) 9(1.5,6) 10(0.6,5.6) 11(1.5,5.2) 12(0.6,4.8) 13(1.5,4.4) 14(0.6,4) 34(9.9,1.6) 35(9.9,2.4) 36(9,2.8) 37(9.9,3.2) 38(9,3.6) 39(9.9,4) 40(9,4.4) 41(9.9,4.8) 42(9,5.2) 43(9,6) 44(9.9,6.4) 45(9,6.8) 46(9.9,7.2) 47(9,7.6) 48(9.9,8) 49(9,8.4) 50(9,9.2) 51(9.9,9.6) 52(9,10) 53(9.9,10.4) 54(9,10.8) 55(9.9,11.5)
  rect 0.4x0.6 smd: 15(0.45,0.6) 16(1.25,0.6) 17(2.05,0.6) 18(2.85,0.6) 19(3.25,1.5) 20(3.65,0.6) 21(4.05,1.5) 22(4.45,0.6) 23(4.85,1.5) 24(5.25,0.6) 25(5.65,1.5) 26(6.05,0.6) 27(6.45,1.5) 28(6.85,0.6) 29(7.25,1.5) 30(7.65,0.6) 31(8.45,0.6) 32(9.25,0.6) 33(10.05,0.6) 56(3.25,7.2) 57(4.05,7.2) 58(4.85,7.2) 59(5.65,7.2) 60(6.45,7.2) 61(7.25,7.2)
  Top keep-out region: 2.95,11.7 4.55,11.7 4.55,10.5 2.95,10.5 2.95,11.7
  silkscreen extent 0,0 10.5,15.5
MSOP8 [mm]
  oval 0.4x1.5 smd: 1(-0.975,-2.25) 2(-0.325,-2.25) 3(0.325,-2.25) 4(0.975,-2.25) 5(0.975,2.25) 6(0.325,2.25) 7(-0.325,2.25) 8(-0.975,2.25)
  silkscreen extent -1.55,-1.3 1.47,1.25
QFN12_2R00X3R00X1R00 [mm]
  rect 1.5x0.25 smd mask+0.025: 1(-0.55,0.5) 2(-0.55,-0.5) 7(0.55,0)
  rect 0.25x0.7 smd mask+0.025: 3(-0.75,-1.45) 4(-0.25,-1.45) 5(0.25,-1.45) 6(0.75,-1.45) 9(0.75,1.45) 10(0.25,1.45) 11(-0.25,1.45) 12(-0.75,1.45)
  rect 0.7x0.25 smd mask+0.025: 8(0.95,0.5)
  silkscreen extent -1.81,0.33 -1.5,0.64
QFN24 [mil]
  rect 11.81x31.5 smd: 1(-44.79,-76.29) 2(-25.11,-76.29) 3(-5.42,-76.29) 4(14.26,-76.29) 5(33.95,-76.29) 6(53.63,-76.29) 13(53.63,81.19) 14(33.95,81.19) 15(14.26,81.19) 16(-5.42,81.19) 17(-25.11,81.19) 18(-44.79,81.19)
  rect 31.5x11.81 smd: 7(83.16,-46.76) 8(83.16,-27.08) 9(83.16,-7.39) 10(83.16,12.29) 11(83.16,31.98) 12(83.16,51.66) 19(-74.32,51.66) 20(-74.32,31.98) 21(-74.32,12.29) 22(-74.32,-7.39) 23(-74.32,-27.08) 24(-74.32,-46.76)
  rect 106.3x106.3 smd: 25(4.42,2.45)
  silkscreen extent -95,-93 87,81
R0402 [mm]
  rect 0.5x0.5 smd: 1(-0.4,0) 2(0.4,0)
  silkscreen extent -0.8,-0.4 0.8,0.4
R0603 [mm]
  rect 0.7x0.9 smd: 1(-0.7,0) 2(0.7,0)
  silkscreen extent -1.2,-0.6 1.2,0.6
R0805 [mil]
  rect 53x55 smd: 1(-35.43,0) 2(35.43,0)
  silkscreen extent -71,-39 71,39
R1206 [mm]
  rect 1.6x1.6 smd: 1(-1.6,0) 2(1.5,0)
  silkscreen extent -2.79,-1.27 2.79,1.27
RJ-45-HR911105B [mil]
  round 149.61 hole 149.61: 0(-222,30) 0/2(233,30)
  rect 62x62 hole 28: 1(176.89,-218.37)
  round 62 hole 28: 2(126.89,-318.37) 3(76.89,-218.37) 4(26.89,-318.37) 5(-23.11,-218.37) 6(-73.11,-318.37) 7(-123.11,-218.37) 8(-173.11,-318.37)
  round 62 hole 40: 9(263,221) 10(163,222) 11(-156,221) 12(-256,222)
  rect 86.61x86.61 hole 70.87: 13(-293,-96) 14(302,-94)
  silkscreen extent -310,-391 319,411
SMD-2P-1.25 [mm]
  rect 0.6x2.5 smd: 1(0.625,0.25) 2(-0.625,0.25)
  rect 2x2.7 smd: 3(-3.1,-3) 4(3.1,-3)
SOD123 [mm]
  rect 0.91x1.22 smd: 1(1.635,0) 2(-1.635,0)
  silkscreen extent -2.29,-0.81 2.29,0.81
SOD_123 [mm]
  rect 1x1 smd mask+0.05: 1(-1.8,0) 2(1.8,0)
  silkscreen extent -1.11,-0.9 1.13,0.9
SOP8-255-50 [mil]
  rect 24x90 smd: 1(-75,-125) 2(-25,-125) 3(25,-125) 4(75,-125) 5(75,125) 6(25,125) 7(-25,125) 8(-75,125)
  silkscreen extent -117,-162 79,39
SOT23 [mm]
  rect 1x1.4 smd: 1(-0.95,-1.1) 2(0.95,-1.1) 3(0,1.1)
  silkscreen extent -1.68,-2.03 1.68,2.03
SOT23-5 [mm]
  rect 0.65x1.06 smd: 1(-0.95,-1.1) 2(0,-1.1) 3(0.95,-1.1) 4(0.95,1.1) 5(-0.95,1.1)
  silkscreen extent -1.57,-1.88 1.57,1.88
SOT26 [mm]
  oval 1.1x0.6 smd: 1(0,0)
  rect 1.1x0.6 smd: 2(0,-1) 3(0,-2) 4(2.8,-2) 5(2.8,-1) 6(2.8,0)
  silkscreen extent 0.88,-2.5 1.95,0.5
SOT_23_5 [mm]
  oval 1.1x0.6 smd mask+0.05: 1(-1.4,1)
  rect 1.1x0.6 smd mask+0.05: 2(-1.4,0) 3(-1.4,-1) 4(1.4,-1) 5(1.4,1)
  silkscreen extent -2.64,-1.5 0.55,1.5
SSOP20_1 [mm]
  rect 0.4x1.3 smd: 1(0,0) 2(0.65,0) 3(1.3,0) 4(1.95,0) 5(2.6,0) 6(3.25,0) 7(3.9,0) 8(4.55,0) 9(5.2,0) 10(5.85,0) 11(5.85,7.7) 12(5.2,7.7) 13(4.55,7.7) 14(3.9,7.7) 15(3.25,7.7) 16(2.6,7.7) 17(1.95,7.7) 18(1.3,7.7) 19(0.65,7.7) 20(0,7.7)
  silkscreen extent -0.88,-0.65 6.58,6.9
SSOP28-HUB [mil]
  oval 70x13 smd: 1(-102.76,155.12) 2(-102.76,129.52) 3(-102.76,103.92) 4(-102.76,78.32) 5(-102.76,52.72) 6(-102.76,27.12) 7(-102.76,1.52) 8(-102.76,-24.08) 9(-102.76,-49.68) 10(-102.76,-75.28) 11(-102.76,-100.88) 12(-102.76,-126.48) 13(-102.76,-152.08) 14(-102.76,-177.68) 15(94.57,-177.68) 16(94.57,-152.08) 17(94.57,-126.48) 18(94.57,-100.88) 19(94.57,-75.28) 20(94.57,-49.68) 21(94.57,-24.08) 22(94.57,1.52) 23(94.57,27.12) 24(94.57,52.72) 25(94.57,78.32) 26(94.57,103.92) 27(94.57,129.52) 28(94.57,155.12)
  silkscreen extent -57,-186 50,164
T-1 [mm]
  round 1 smd: 1(0,0)
TF-CKT01-009D [mm]
  rect 1.6x0.7 smd: 1(-10.516,3.2) 2(-10.516,2.1) 3(-10.516,1) 4(-10.516,-0.1) 5(-10.516,-1.2) 6(-10.516,-2.3) 7(-10.516,-3.4) 8(-10.516,-4.5) 9(-10.516,-5.6)
  rect 1.6x1.4 smd: 10(-10.016,-7) 13(-10.016,8.7)
  rect 2.2x1.2 smd: 11(-0.416,-6.8) 12(-0.416,8.7)
  round 0.9 hole 0.9 unplated: 14(0,4) 15(0,-4)
  silkscreen extent -10.52,-6.4 3.98,8.3
TS-1038 [mm]
  round 1.5 / inner round 1.524 / far side round 1.8 hole 1.1: 1(-2.25,0) 2(2.25,0)
  round 2 hole 1.4: 3(-3.4,2.5) 4(3.4,2.5)
  silkscreen extent -3.6,-6.1 3.8,4
TYPEC-16PIN-SMD1 [mm]
  round 0.65 hole 0.65: 6(-7.195,3.2) 7(-1.445,3.2)
  rect 0.6x1.15 smd: A1(-7.52,4.75) A4(-6.72,4.75) A9(-1.92,4.75) A12(-1.12,4.75) B1(-1.12,4.75) B4(-1.92,4.75) B9(-6.72,4.75) B12(-7.52,4.75)
  rect 0.3x1.15 smd: A5(-5.57,4.75) A6(-4.57,4.75) A7(-4.07,4.75) A8(-6.07,4.75) B5(-2.57,4.75) B6(-3.57,4.75) B7(-5.07,4.75) B8(-3.07,4.75)
  oval 0.7x1.8 / inner oval 0.7x1.5 / far side oval 1x1.9 hole 0.6 slot 1.5 at 90 deg: E1(-8.64,0) E2(0,0)
  oval 0.7x1.9 / inner oval 0.7x1.8 / far side oval 1x2.1 hole 0.6 slot 1.5 at 90 deg: E3(-8.64,4.15) E4(0,4.15)
  silkscreen extent -8.64,-2.28 0,4.67
USB-AF-DUAL [mm]
  round 1.3 / inner round 0.9 / far side round 1.3 hole 0.9: 1(3.18,3.5) 2(3.18,1) 3(3.18,-1) 4(3.18,-3.5) 5(5.68,3.5) 6(5.68,1) 7(5.68,-1) 8(5.68,-3.5)
  round 3.048 / inner round 2.5 / far side round 3.048 hole 2.3: 9(0,6.7)
  round 3.048 / inner round 2.5 / far side round 3.048 hole 2.286: 10(0,-6.7) 11(5.7,6.7) 12(5.7,-6.7)
  silkscreen extent -9.97,-7.52 7.1,7.81

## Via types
v1: diameter 15.75, hole 7.87, Top to Bottom, 1478 vias
v2: diameter 19.68, hole 11.81, Top to Bottom, 38 vias

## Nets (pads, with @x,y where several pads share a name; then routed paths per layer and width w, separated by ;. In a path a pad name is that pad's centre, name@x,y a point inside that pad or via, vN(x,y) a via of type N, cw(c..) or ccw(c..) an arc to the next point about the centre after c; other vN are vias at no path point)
5V: C7.1 C13.1 C27.1 C29.1 C70.2 C71.2 C74.1 C77.2 C78.2 C79.2 C80.2 CON1.37 CON1.38 D15.2 J1.4 J1.5 L1.1 R28.1 R46.2 R61.2 U1.111 U1.112 U3.1 U4.6 U6.30 U13.5 U14.20 | length 1687.7
  Top w3.94: -2780.53,271.65 -2780.53,274.59 v1(-2771.65,283.46) ; -2777.56,271.65 -2771.65,265.75 v1(-2771.65,259.84)
  Top w11.81: -3413.39,271.65 J1.4@-3413.39,440.94 ; -3393.7,271.65 J1.5@-3393.7,440.94 ; U14.20@-2640.23,368.03 -2640.23,253.94 -2631.89,245.59 -2632.36,245.59 C74.1@-2633.86,244.09
  Top w15.75: C27.1@-580.71,1911.42 -564.96,1927.17 -559.06,1927.17 U6.30@-559.06,2009.84
  Top w19.68: C29.1@-387.8,1954.72 v2(-387.8,1982.28) R46.2@-387.8,2005.91
  Top w39.37: R61.2@-3779.53,336.61 -3643.7,336.61 -3578.74,271.65 -3413.39,271.65 -3393.7,271.65 -2780.53,271.65 -2777.56,271.65
  other v1: -2814.96,259.84 -2793.31,259.84 -2653.54,269.68 -2629.92,269.68 -2814.96,283.46 -2793.31,283.46 -2653.54,295.28 -3555.12,1344.49 -3525.59,1344.49 -3470.47,1344.49 -3555.12,1366.14 -3525.59,1366.14 -3470.47,1366.14 -3500,1466.54 -3478.35,1466.54 -3500,1488.19 -3478.35,1488.19 -602.36,1885.83 -580.71,1885.83 -559.06,1885.83 -3708.66,2139.76 -3687.01,2139.76 -3665.35,2139.76 -3708.66,2218.5 -3687.01,2218.5 -3665.35,2218.5 -3708.66,2240.16 -3687.01,2240.16 -3665.35,2240.16 -3708.66,2259.84 -3687.01,2259.84 -3665.35,2259.84
  other v2: -2185.04,501.97 -2161.42,501.97 -2137.8,501.97 -2185.04,527.56 -2161.42,527.56 -2137.8,527.56 -2507.87,690.94 -2484.25,690.94 -2460.63,690.94 -2507.87,716.54 -2484.25,716.54 -2460.63,716.54 -559.06,1625.98 -535.43,1625.98 -511.81,1625.98 -559.06,1651.57 -535.43,1651.57 -511.81,1651.57
ADC_IN0: C26.1 CON1.8 J11.2 R32.2 SW2.2 U1.102 | length 6763.2
  Top w3.94: U1.102@-2862.2,755.91 -2862.2,791.34 -2856.3,797.24 -2108.27,797.24 v1(-2090.55,814.96) ; v1(-2015.75,814.96) -2000,799.21 -1972.44,799.21 -1903.54,868.11 -1903.54,992.13 -1883.86,1011.81 -66.93,1011.81 -37.4,1041.34 v1(-37.4,1287.4) ; v1(-1230.31,2541.34) v1(-935.04,2541.34)
  Top w15.75: SW2.2@-1484.25,2448.82 R32.2@-1484.25,2362.2 C26.1@-1444.88,2362.2 -1444.88,2529.53 -1433.07,2541.34 v1(-1230.31,2541.34) ; v1(-1230.31,2610.24) J11.2@-1230.31,2653.54
  Bottom w3.94: v1(-2090.55,814.96) v1(-2015.75,814.96) ; v1(-935.04,2541.34) -919.29,2541.34 -832.68,2627.95 -287.4,2627.95 -265.75,2649.61 -108.27,2649.61 -74.8,2616.14 -74.8,2013.78 -84.65,2003.94 -220.47,2003.94 -248.03,1976.38 -248.03,1393.7 -155.51,1301.18 -51.18,1301.18 v1(-37.4,1287.4)
  Bottom w15.75: v1(-1230.31,2541.34) v1(-1230.31,2610.24)
ADC_IN2: CON1.12 U1.100 | length 3707.7
  Top w3.94: U1.100@-2940.94,755.91 -2940.94,803.15 -2931.1,812.99 -2137.8,812.99 -2122.05,828.74 -1978.35,828.74 -1919.29,887.8 -1919.29,1001.97 -1893.7,1027.56 -78.74,1027.56 -59.06,1047.24 -59.06,1501.97 -82.68,1525.59 -163.39,1525.59 CON1.12@-192.91,1496.06
ADC_IN3: C1.1 CON1.7 J6.7 R1.2 R3.1 U1.99 | length 7376
  Top w3.94: R1.2@-2905.51,690.94 C1.1@-2942.91,690.94 -2948.82,690.94 R3.1@-2980.31,690.94 U1.99@-2980.31,755.91 -2980.31,812.99 -2972.44,820.87 -2141.73,820.87 -2125.98,836.61 -1982.28,836.61 -1927.17,891.73 -1927.17,1005.91 -1897.64,1035.43 -82.68,1035.43 -66.93,1051.18 -66.93,1316.93 -88.58,1338.58 CON1.7@-114.17,1338.58 ; J6.7@-2196.85,2594.49 -2196.85,2627.95 -2188.98,2635.83 -1702.76,2635.83 -1653.54,2586.61 -937.01,2586.61 v1(-915.35,2608.27)
  Bottom w3.94: v1(-915.35,2608.27) -868.11,2608.27 -838.58,2637.8 -293.31,2637.8 -267.72,2663.39 -104.33,2663.39 -66.93,2625.98 -66.93,1940.94 -74.8,1933.07 -222.44,1933.07 -240.16,1915.35 -240.16,1401.57 -216.54,1377.95 -173.23,1377.95 -157.48,1362.2 -157.48,1346.46 -149.61,1338.58 CON1.7@-114.17,1338.58
ADC_IN4: CON1.9 U1.98 | length 3821
  Top w3.94: U1.98@-3019.69,755.91 -3019.69,807.09 -2998.03,828.74 -2145.67,828.74 -2129.92,844.49 -1986.22,844.49 -1935.04,895.67 -1935.04,1009.84 -1901.57,1043.31 -88.58,1043.31 -74.8,1057.09 -74.8,1283.46 -92.52,1301.18 -220.47,1301.18 -230.31,1311.02 -230.31,1438.98 -220.47,1448.82 -145.67,1448.82 CON1.9@-114.17,1417.32
ADC_IN5: CON1.11 U1.97 | length 3875.9
  Top w3.94: U1.97@-3059.06,755.91 -3059.06,809.06 -3031.5,836.61 -2149.61,836.61 -2133.86,852.36 -1994.09,852.36 -1942.91,903.54 -1942.91,1015.75 -1907.48,1051.18 -92.52,1051.18 -82.68,1061.02 -82.68,1277.56 -94.49,1289.37 -228.35,1289.37 -242.13,1303.15 -242.13,1442.91 -224.41,1460.63 -149.61,1460.63 CON1.11@-114.17,1496.06
ADC_KEY_IN1: CON1.10 J6.8 U1.101 | length 7269.7
  Top w3.94: U1.101@-2901.57,755.91 -2901.57,797.24 -2893.7,805.12 -2124.02,805.12 v1(-2114.17,814.96) ; J6.8@-2216.54,2594.49 -2216.54,2641.73 -2208.66,2649.61 -1694.88,2649.61 -1641.73,2596.46 -952.76,2596.46 v1(-940.94,2608.27) ; v1(-1984.25,814.96) -1970.47,814.96 -1911.42,874.02 -1911.42,998.03 -1889.76,1019.68 -72.83,1019.68 -51.18,1041.34 -51.18,1364.17 v1(-37.4,1377.95)
  Bottom w3.94: v1(-2114.17,814.96) -2098.43,799.21 -2000,799.21 v1(-1984.25,814.96) ; v1(-940.94,2608.27) -927.17,2622.05 -868.11,2622.05 -842.52,2647.64 -299.21,2647.64 -273.62,2673.23 -90.55,2673.23 -55.12,2637.8 -55.12,1938.98 -68.9,1925.2 -216.54,1925.2 -232.28,1909.45 -232.28,1456.69 CON1.10@-192.91,1417.32 -153.54,1377.95 v1(-37.4,1377.95)
B_DM3: U7.7 U14.6 | length 1641.2
  Top w5.91: v1(-3820.87,482.28) -3820.87,504.94 U7.7@-3820.38,505.42 ; U14.6@-2563.43,565.35 -2562.99,564.91 v1(-2562.99,523.62)
  Bottom w5.91: v1(-3820.87,482.28) -3815.94,477.36 -3815.94,381.75 -3643.84,209.65 -2982.28,209.65 -2727.36,464.57 -2589.5,464.57 -2570.87,483.2 -2570.87,515.75 v1(-2562.99,523.62)
B_DM4: R45.2 U14.4 | length 3401
  Top w5.91: U14.4@-2512.23,565.35 -2512.23,593.85 -2520.11,601.73 -2520.11,614.03 -2510.13,624.02 -2182.93,624.02 -2154.39,652.56 -2005.91,652.56 -1937.99,720.47 -1937.99,781.36 -1741.6,977.75 -680.58,977.75 -678.15,975.32 -678.15,959.65 v1(-683.07,954.72) ; R45.2@-387.8,2045.28 v1(-372.05,2045.28)
  Bottom w5.91: v1(-683.07,954.72) -678.15,959.65 -678.15,1116.14 -481.3,1312.99 -481.3,1694.88 -342.52,1833.66 -342.52,2050.06 -352.5,2060.04 -366.14,2060.04 -372.05,2054.13 v1(-372.05,2045.28)
B_DP3: U7.8 U14.7 | length 1608.6
  Top w5.91: v1(-3801.18,482.28) -3801.18,504.94 U7.8@-3800.7,505.42 ; U14.7@-2589.03,565.35 -2588.58,564.9 v1(-2588.58,523.62)
  Bottom w5.91: v1(-3801.18,482.28) -3806.1,477.36 -3806.1,385.83 -3639.76,219.49 -2986.36,219.49 -2731.44,474.41 -2593.57,474.41 -2580.71,487.27 -2580.71,515.75 v1(-2588.58,523.62)
B_DP4: R44.2 U14.5 | length 3449.9
  Top w5.91: U14.5@-2537.83,565.35 -2537.83,593.85 -2529.95,601.73 -2529.95,618.11 -2514.21,633.86 -2187.01,633.86 -2158.46,662.4 -2009.98,662.4 -1947.83,724.55 -1947.83,785.43 -1745.68,987.59 -676.5,987.59 -668.31,979.4 -668.31,959.65 v1(-663.39,954.72) ; R44.2@-387.8,2084.65 v1(-372.05,2084.65)
  Bottom w5.91: v1(-663.39,954.72) -668.31,959.65 -668.31,1112.06 -471.46,1308.92 -471.46,1690.81 -332.68,1829.58 -332.68,2054.13 -348.43,2069.88 -366.14,2069.88 -372.05,2075.79 v1(-372.05,2084.65)
BUSJ: C76.1 R86.1 U14.18 U14.19 U14.26 | length 577.6
  Top w11.81: R86.1@-2694.88,179.13 -2681.1,179.13 -2673.23,187.01 -2673.23,246.06 -2681.1,253.94 C76.1@-2694.88,253.94 -2691.43,257.39 U14.18@-2691.43,368.03 -2691.43,411.42 -2681.59,421.26 -2665.83,421.26 ; U14.19@-2665.83,368.03 -2665.83,421.26 ; U14.26@-2486.63,368.03 -2486.63,411.83 -2496.06,421.26 -2665.83,421.26
CC1: J10.B5 R85.2 | length 74.8
  Top w11.81: R85.2@-2214.57,344.49 -2195.67,325.59 J10.B5@-2195.67,277.56
CC2: J10.A5 R84.2 | length 75.1
  Top w11.81: R84.2@-2328.74,346.46 -2313.78,331.5 J10.A5@-2313.78,277.56
CHG_DET: CON1.23 R51.1 U6.47 | length 741.8
  Top w3.94: U6.47@-505.91,2285.43 R51.1@-405.51,2285.43 -385.83,2305.12 -277.56,2305.12 -265.75,2293.31 -265.75,1992.13 -210.63,1937.01 -145.67,1937.01 CON1.23@-114.17,1968.5
DC12V_ADC: R34.1 R35.2 U6.12 | length 5311.4
  Top w15.75: R34.1@-4167.32,1629.92 v1(-4147.64,1629.92) R35.2@-4127.95,1629.92 ; v1(-3643.7,1629.92) v1(-3643.7,2891.73) ; v1(-1005.91,2175.2) U6.12@-836.61,2175.2
  Bottom w15.75: v1(-4147.64,1629.92) v1(-3643.7,1629.92) ; v1(-3643.7,2891.73) -1035.43,2891.73 -1005.91,2862.2 v1(-1005.91,2175.2)
DC-12V: C19.1 J4.1 R29.2 R34.2 R40.2 U5.1 | length 5047.8
  Top w15.75: v1(-4198.82,1608.27) R34.2@-4198.82,1629.92 ; v1(-3622.05,1608.27) v1(-3622.05,2913.39) ; R40.2@-984.25,2383.86 v1(-984.25,2401.57)
  Bottom w15.75: v1(-4198.82,1608.27) v1(-3622.05,1608.27) ; v1(-3622.05,2913.39) -1023.62,2913.39 -984.25,2874.02 v1(-984.25,2401.57)
DC_INT: Q3.3 R39.1 U6.3 | length 185.8
  Top w15.75: Q3.3@-966.54,2293.31 R39.1@-905.51,2293.31 -905.51,2338.58 -879.92,2364.17 U6.3@-836.61,2364.17
DGND: C35.2 C36.2 C37.2 C38.2 C39.2 C40.2 C41.2 C42.2 C43.2 C44.2 C45.2 C46.2 C47.2 C48.2 R54.1 R57.2 U7.6 U7.25 X1.2 X1.4 | length 271.3
  Top w15.75: v1(-3870.08,698.82) C41.2@-3870.08,716.54 ; C42.2@-3801.18,748.03 v1(-3801.18,765.75) ; C40.2@-3763.78,748.03 v1(-3763.78,765.75) ; C39.2@-3722.44,748.03 v1(-3722.44,765.75) ; C43.2@-3610.24,586.61 v1(-3574.8,586.61) ; C35.2@-3606.3,547.24 -3598.43,555.12 v1(-3574.8,555.12)
  Top w19.68: C36.2@-3913.39,602.36 v1(-3913.39,576.77) -3913.39,537.4 -3893.7,517.72 v1(-3856.3,517.72)
  other v1: -3692.91,375.98 -3661.42,375.98 -3852.36,401.57 -3773.62,401.57 -3700.79,403.54 -3911.42,429.13 -3881.89,429.13 -3911.42,450.79 -3881.89,450.79 -3850.39,474.41 -3905.51,501.97 -3517.72,501.97 -3517.72,533.46 -3814.96,539.37 -3771.65,539.37 -3726.38,539.37 -3814.96,582.68 -3771.65,582.68 -3726.38,582.68 -3814.96,627.95 -3771.65,627.95 -3726.38,627.95 -3895.67,702.76 -3620.08,773.62 -3742.13,854.33 -3742.13,875.98 -3712.6,899.61 -3690.94,899.61 -3694.88,919.29 -3675.2,919.29
DISP: FP1.31 R7.1 R8.1 | length 2095.9
  Top w3.94: v1(-1645.67,1966.54) -1625.98,1946.85 FP1.31@-1625.98,1905.51 ; v1(-1625.98,1622.05) v1(-927.17,1622.05) ; R8.1@-994.09,921.26 -980.31,935.04 v1(-801.18,935.04)
  Top w15.75: R7.1@-1031.5,921.26 R8.1@-994.09,921.26
  Bottom w3.94: v1(-1645.67,1966.54) -1625.98,1946.85 v1(-1625.98,1622.05) ; v1(-927.17,1622.05) -927.17,1446.85 -801.18,1320.87 v1(-801.18,935.04)
DM0: D17.1 J10.A7 J10.B7 U1.105 | length 947.4
  Top w5.91: v1(-2744.09,720.47) U1.105@-2744.09,755.91 ; D17.1@-2291.34,346.46 -2293.31,344.49 v1(-2293.31,307.09) -2294.09,306.3 J10.B7@-2294.09,277.56 -2294.09,248.82 -2289.37,244.09 -2258.66,244.09 -2254.72,248.03 J10.A7@-2254.72,277.56
  Bottom w5.91: v1(-2744.09,720.47) -2729.33,705.71 -2729.33,688.98 -2715.55,675.2 -2545.42,675.2 -2523.76,653.54 -2460.77,653.54 -2288.39,481.16 -2288.39,323.82 -2293.31,318.9 v1(-2293.31,307.09)
DM1: ED8.1 J9.2 U14.10 | length 2328.7
  Top w5.91: J9.2@-4280.31,1177.17 -4280.31,1147.64 -4275.39,1142.72 -4246.13,1142.72 -4235.24,1153.61 -4235.24,1210.7 -4218.57,1227.36 -4129.99,1227.36 -4126.97,1230.38 -4126.97,1278.02 -4117.59,1287.4 -4097.83,1287.4 ED8.1@-4072.24,1312.99 -4065.24,1305.99 -4046.65,1287.4 -3983.2,1287.4 -3894.62,1198.82 -3529.53,1198.82 v1(-3523.62,1204.72) ; v1(-2669.29,612.2) -2673.96,607.53 -2673.96,601.48 -2666.08,593.6 -2665.83,593.85 U14.10@-2665.83,565.35
  Bottom w5.91: v1(-3523.62,1204.72) -3517.72,1198.82 -3496.06,1198.82 -3448.82,1151.57 -3448.82,883.86 -3383.86,818.9 -3383.86,748.17 -3314.82,679.13 -3204.72,679.13 -2903.54,679.13 -2864.17,679.13 -2828.74,643.7 -2789.37,643.7 -2738.19,643.7 -2686.87,643.7 -2674.21,631.05 -2674.21,617.13 v1(-2669.29,612.2)
DM2: ED10.1 J9.6 U14.8 | length 2274.2
  Top w5.91: J9.6@-4181.89,1177.17 -4181.89,1147.64 -4176.97,1142.72 -4152.7,1142.72 -4118.25,1177.17 -4095.87,1177.17 ED10.1@-4072.24,1200.79 -4065.24,1193.79 -4048.62,1177.17 -3984.25,1177.17 -3952.76,1145.67 -3529.53,1145.67 v1(-3523.62,1151.57) ; v1(-2830.71,488.19) -2825.79,493.11 -2635.76,493.11 -2622.51,506.36 -2622.51,528.98 -2614.63,536.85 U14.8@-2614.63,565.35
  Bottom w5.91: v1(-3523.62,1151.57) -3517.72,1145.67 -3500,1145.67 -3484.25,1129.92 -3484.25,872.05 -3415.35,803.15 -3415.35,738.33 -3316.79,639.76 -2875.98,639.76 -2797.24,561.02 -2797.24,503.94 -2808.07,493.11 -2825.79,493.11 v1(-2830.71,488.19)
DP0: D16.1 J10.A6 J10.B6 U1.106 | length 929.3
  Top w5.91: v1(-2704.72,720.47) U1.106@-2704.72,755.91 ; J10.A6@-2274.41,277.56 v1@-2274.41,306.3 ; v1(-2273.62,307.09) v1@-2274.41,306.3 ; J10.B6@-2235.04,277.56 -2235.04,328.74 -2250.79,344.49 D16.1@-2253.94,344.49 -2274.41,324.02 v1@-2274.41,306.3
  Bottom w5.91: v1(-2704.72,720.47) -2719.49,705.71 -2719.49,693.05 -2711.47,685.04 -2541.34,685.04 -2519.69,663.39 -2456.69,663.39 -2278.54,485.24 -2278.54,323.82 -2273.62,318.9 v1(-2273.62,307.09)
DP1: ED7.1 J9.3 U14.11 | length 2311.9
  Top w5.91: J9.3@-4280.31,1098.43 -4280.31,1127.95 -4275.39,1132.87 -4242.06,1132.87 -4225.39,1149.54 -4225.39,1206.62 -4214.5,1217.52 -4125.91,1217.52 -4117.13,1226.31 -4117.13,1273.95 -4113.51,1277.56 -4097.83,1277.56 ED7.1@-4072.24,1251.97 -4064.74,1259.47 -4046.65,1277.56 -3987.27,1277.56 -3898.69,1188.98 -3529.53,1188.98 v1(-3523.62,1183.07) ; U14.11@-2691.43,565.35 -2691.43,593.85 -2683.8,601.48 -2683.8,607.03 v1(-2688.98,612.2)
  Bottom w5.91: v1(-3523.62,1183.07) -3517.72,1188.98 -3500.14,1188.98 -3458.66,1147.5 -3458.66,879.78 -3393.7,814.82 -3393.7,744.09 -3318.9,669.29 -2868.25,669.29 -2832.82,633.86 -2828.74,633.86 -2690.94,633.86 -2684.06,626.97 -2684.06,617.13 v1(-2688.98,612.2)
DP2: ED9.1 J9.7 U14.9 | length 2225.3
  Top w5.91: J9.7@-4181.89,1098.43 -4181.89,1127.95 -4176.97,1132.87 -4148.62,1132.87 -4114.17,1167.32 -4095.87,1167.32 ED9.1@-4072.24,1143.7 -4064.74,1151.2 -4048.62,1167.32 -3988.33,1167.32 -3956.83,1135.83 -3529.53,1135.83 v1(-3523.62,1129.92) ; v1(-2830.71,507.87) -2825.79,502.95 -2639.83,502.95 -2632.35,510.43 -2632.35,528.98 -2640.23,536.85 U14.9@-2640.23,565.35
  Bottom w5.91: v1(-3523.62,1129.92) -3517.72,1135.83 -3504.08,1135.83 -3494.09,1125.84 -3494.09,867.97 -3425.2,799.07 -3425.2,734.25 -3320.87,629.92 -3226.38,629.92 -2880.06,629.92 -2807.09,556.95 -2807.09,508.01 -2812.15,502.95 -2825.79,502.95 v1(-2830.71,507.87)
DRV: R88.2 U14.22 | length 179.2
  Top w11.81: U14.22@-2589.03,368.03 -2589.03,303.15 -2576.77,290.89 -2521.65,290.89 -2509.84,279.08 R88.2@-2509.84,253.94
EMMC_CLK: U1.52 | length 770.9
  Top w3.94: v1(-3218.5,2598.43) -3218.5,2618.11 ; v1(-3043.31,2631.89) -3043.31,2261.81 -3025.59,2244.09 v1(-2980.31,2244.09) ; U1.52@-2980.31,2133.86 v1(-2980.31,2169.29)
  Bottom w3.94: v1(-3218.5,2598.43) -3218.5,2618.11 -3212.6,2624.02 -3051.18,2624.02 v1(-3043.31,2631.89) ; v1(-2980.31,2169.29) v1(-2980.31,2244.09)
EMMC_CMD: U1.53 | length 744.1
  Top w3.94: v1(-3198.82,2598.43) -3198.82,2618.11 ; U1.53@-3019.69,2133.86 v1(-3019.69,2169.29) ; v1(-3019.69,2261.81) -3031.5,2273.62 -3031.5,2608.27 v1(-3007.87,2631.89)
  Bottom w3.94: v1(-3198.82,2598.43) -3198.82,2610.24 -3194.88,2614.17 -3025.59,2614.17 v1(-3007.87,2631.89) ; v1(-3019.69,2169.29) v1(-3019.69,2261.81)
EMMC_D0: U1.57 | length 281.6
  Top w3.94: U1.57@-3177.17,2133.86 v1(-3177.17,2169.29) ; -3159.45,2401.57 -3159.45,2320.87 v1(-3151.57,2312.99)
  Bottom w3.94: v1(-3177.17,2169.29) -3177.17,2287.4 v1(-3151.57,2312.99)
EMMC_D1: U1.56 | length 348.6
  Top w3.94: -3179.13,2401.57 -3179.13,2297.24 -3125.98,2244.09 v1(-3098.43,2244.09) ; U1.56@-3137.8,2133.86 v1(-3137.8,2169.29)
  Bottom w3.94: v1(-3137.8,2169.29) -3137.8,2230.31 -3124.02,2244.09 v1(-3098.43,2244.09)
EMMC_D2: U1.55 | length 347.4
  Top w3.94: -3198.82,2401.57 -3198.82,2251.97 -3163.39,2216.54 v1(-3098.43,2216.54) ; U1.55@-3098.43,2133.86 v1(-3098.43,2169.29)
  Bottom w3.94: v1(-3098.43,2169.29) v1(-3098.43,2216.54)
EMMC_D3: U1.54 | length 332.9
  Top w3.94: -3139.76,2421.26 -3149.61,2411.42 -3149.61,2332.68 -3059.06,2242.13 v1(-3059.06,2244.09) ; U1.54@-3059.06,2133.86 v1(-3059.06,2169.29)
  Bottom w3.94: v1(-3059.06,2169.29) v1(-3059.06,2244.09)
EMMC_D4: U1.51 | length 476
  Top w3.94: -3159.45,2421.26 -3169.29,2411.42 -3169.29,2305.12 -3161.42,2297.24 -3131.89,2297.24 -3064.96,2230.31 v1(-2940.94,2230.31) ; U1.51@-2940.94,2133.86 v1(-2940.94,2169.29)
  Bottom w3.94: v1(-2940.94,2169.29) v1(-2940.94,2230.31)
EMMC_D5: U1.50 | length 533.9
  Top w3.94: -3179.13,2421.26 -3188.98,2411.42 -3188.98,2293.31 -3125.98,2230.31 -3088.58,2230.31 -3074.8,2216.54 v1(-2901.57,2216.54) ; U1.50@-2901.57,2133.86 v1(-2901.57,2169.29)
  Bottom w3.94: v1(-2901.57,2169.29) v1(-2901.57,2216.54)
EMMC_D6: U1.49 | length 643
  Top w3.94: -3198.82,2421.26 -3208.66,2411.42 -3208.66,2344.49 -3234.25,2318.9 -3234.25,2255.91 -3181.1,2202.76 v1(-2862.2,2202.76) ; U1.49@-2862.2,2133.86 v1(-2862.2,2169.29)
  Bottom w3.94: v1(-2862.2,2169.29) v1(-2862.2,2202.76)
EMMC_D7: U1.48 | length 677.7
  Top w3.94: -3218.5,2421.26 -3227.78,2411.98 -3227.78,2393.7 -3244.09,2377.39 -3244.09,2248.03 -3185.04,2188.98 -2834.65,2188.98 -2822.83,2177.17 U1.48@-2822.83,2133.86
ETH_RX+: JP1.3 U7.4 | length 436.9
  Top w3.94: v1(-3874.02,574.8) -3850.39,574.8 U7.4@-3849.91,574.32
  Bottom w3.94: JP1.3@-4155.65,517.84 -4165.24,517.84 -4188.98,494.09 -4188.98,483.15 -4182.2,476.38 -4135.83,476.38 -4096.46,515.75 -3950.79,515.75 -3897.64,568.9 -3879.92,568.9 v1(-3874.02,574.8)
ETH_RX-: JP1.6 U7.5 | length 437.3
  Top w3.94: v1(-3874.02,555.12) -3850.4,555.12 U7.5@-3849.91,554.63
  Bottom w3.94: JP1.6@-4055.65,367.83 -4110.24,422.43 -4110.24,490.16 -4092.52,507.87 -3946.85,507.87 -3893.7,561.02 -3879.92,561.02 v1(-3874.02,555.12)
